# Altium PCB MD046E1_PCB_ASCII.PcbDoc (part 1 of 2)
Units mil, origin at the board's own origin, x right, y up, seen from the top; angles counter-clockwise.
Board outline 4143.7 x 2795.28 mil, 4 copper layers (Top Layer, Signal Layer 1, Signal Layer 2, Bottom Layer), stack 62.8 mil thick; 159 components, 76 nets, 432 pads, 579 vias.
Unrouted connection lines stored in the file: 13.
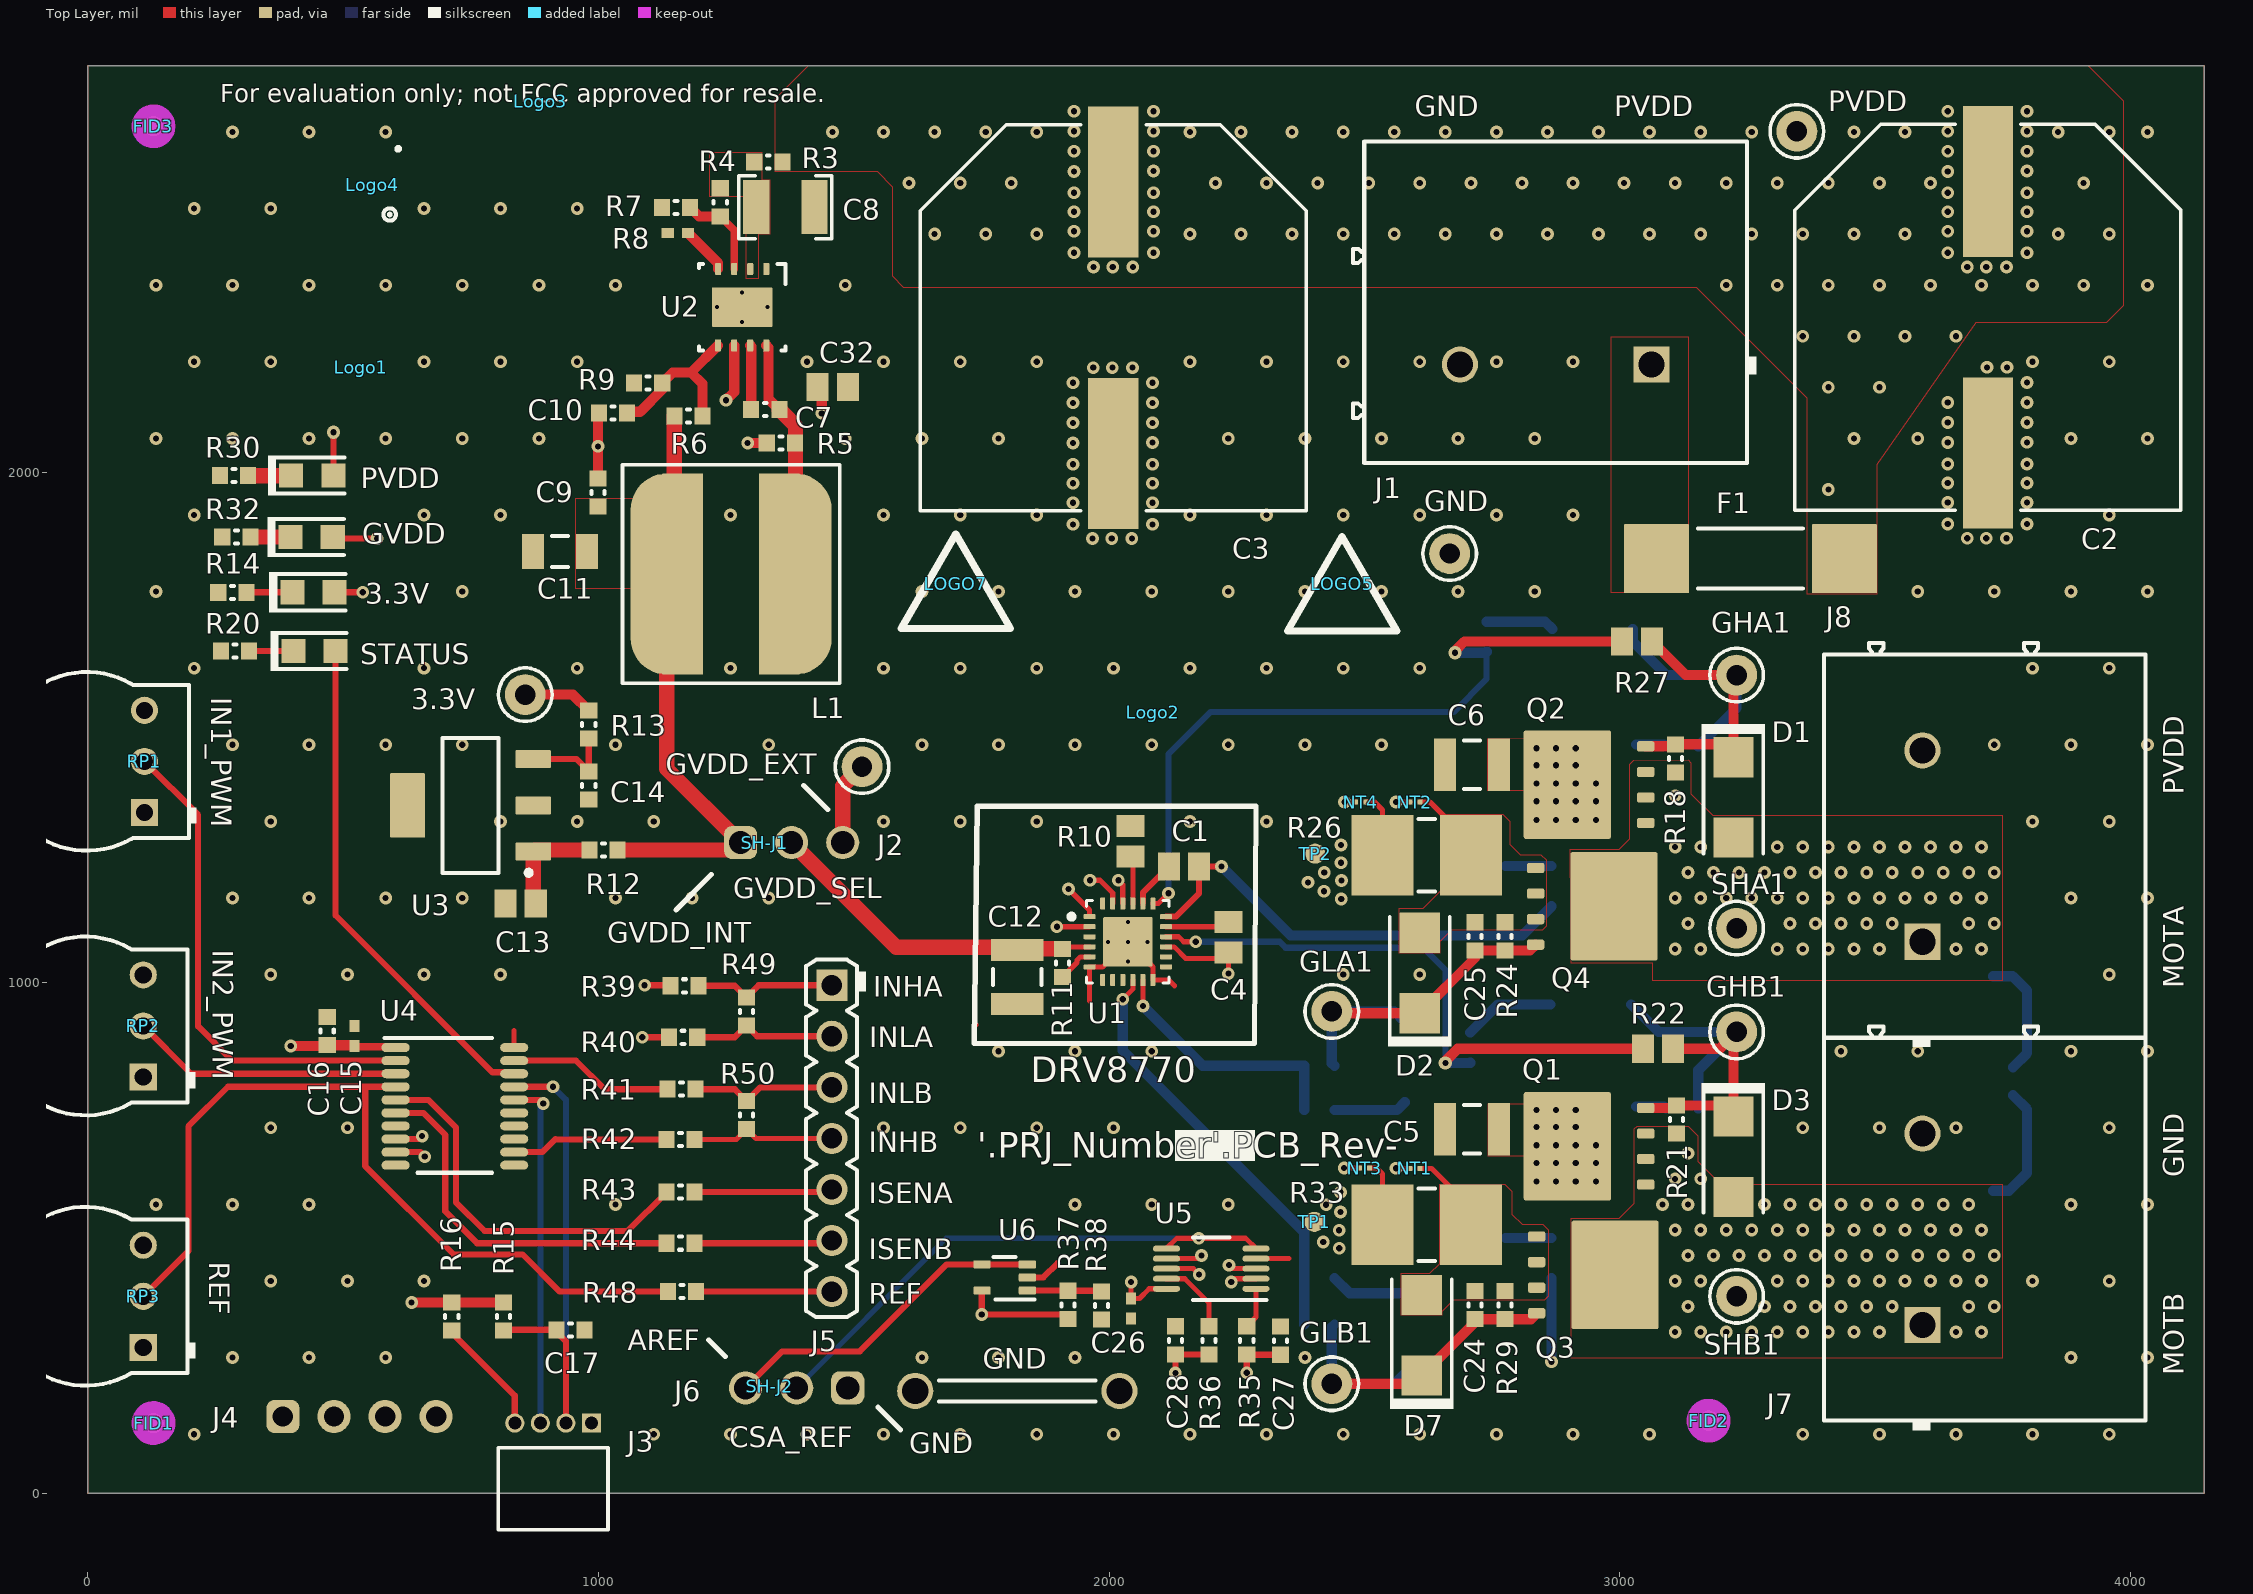
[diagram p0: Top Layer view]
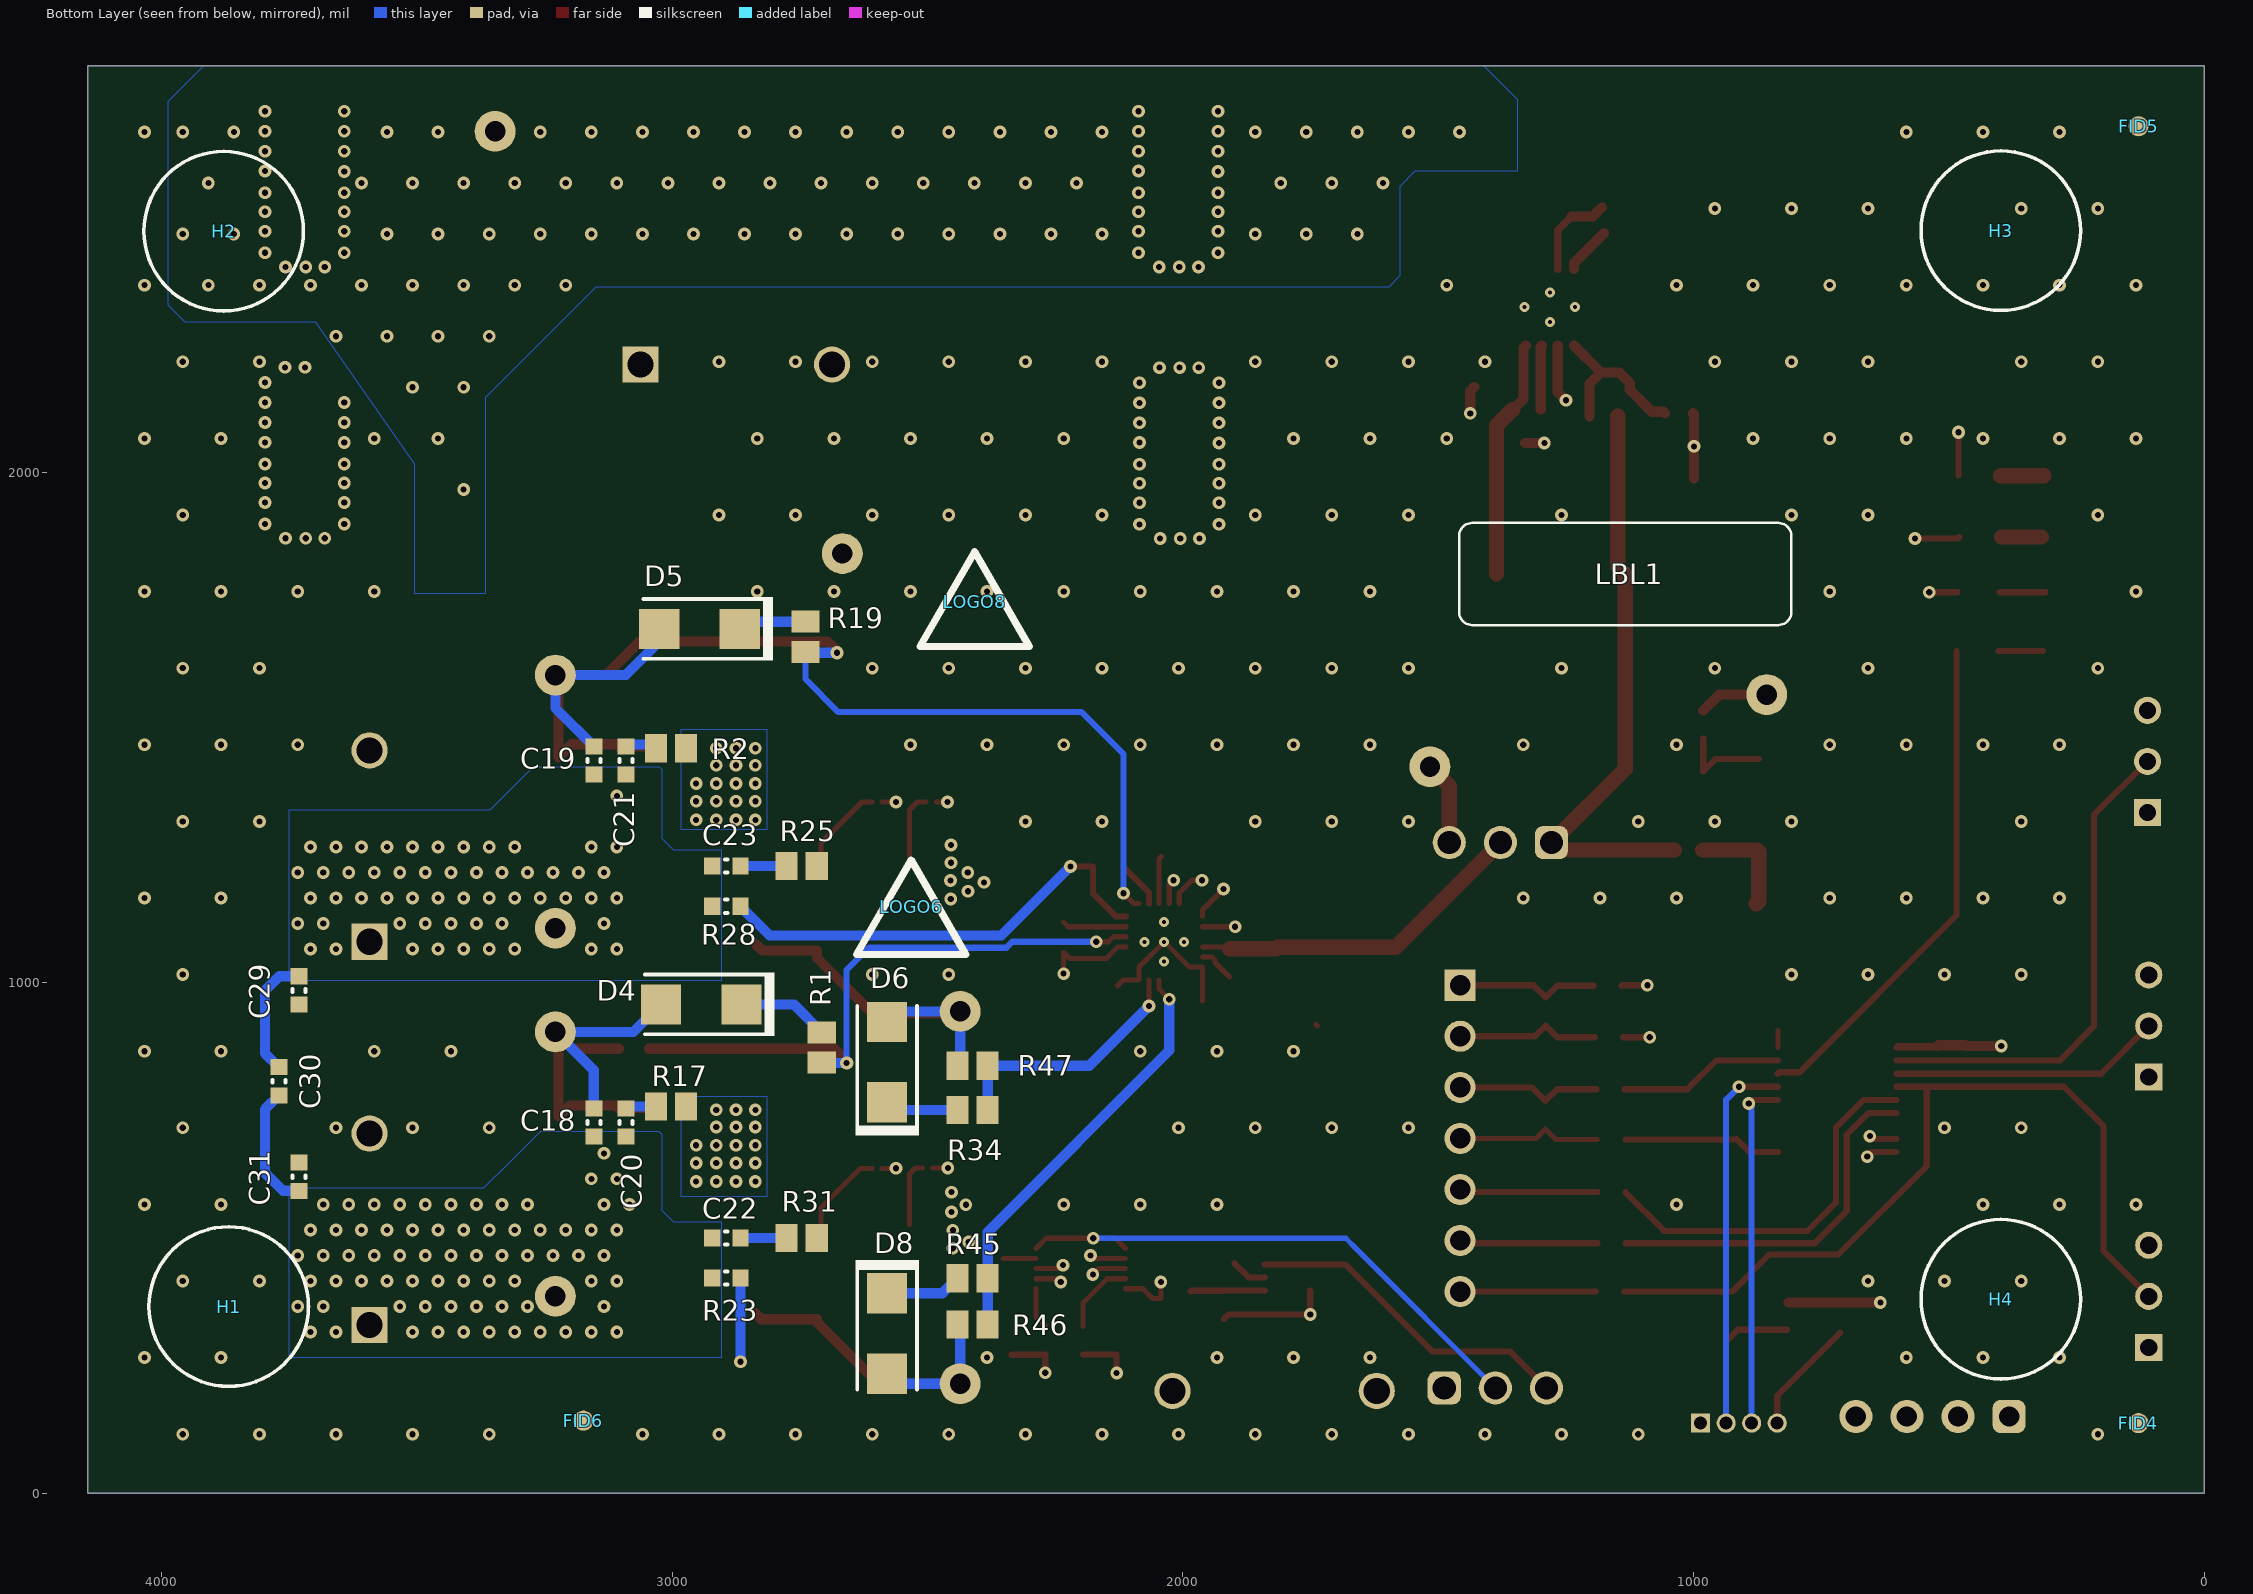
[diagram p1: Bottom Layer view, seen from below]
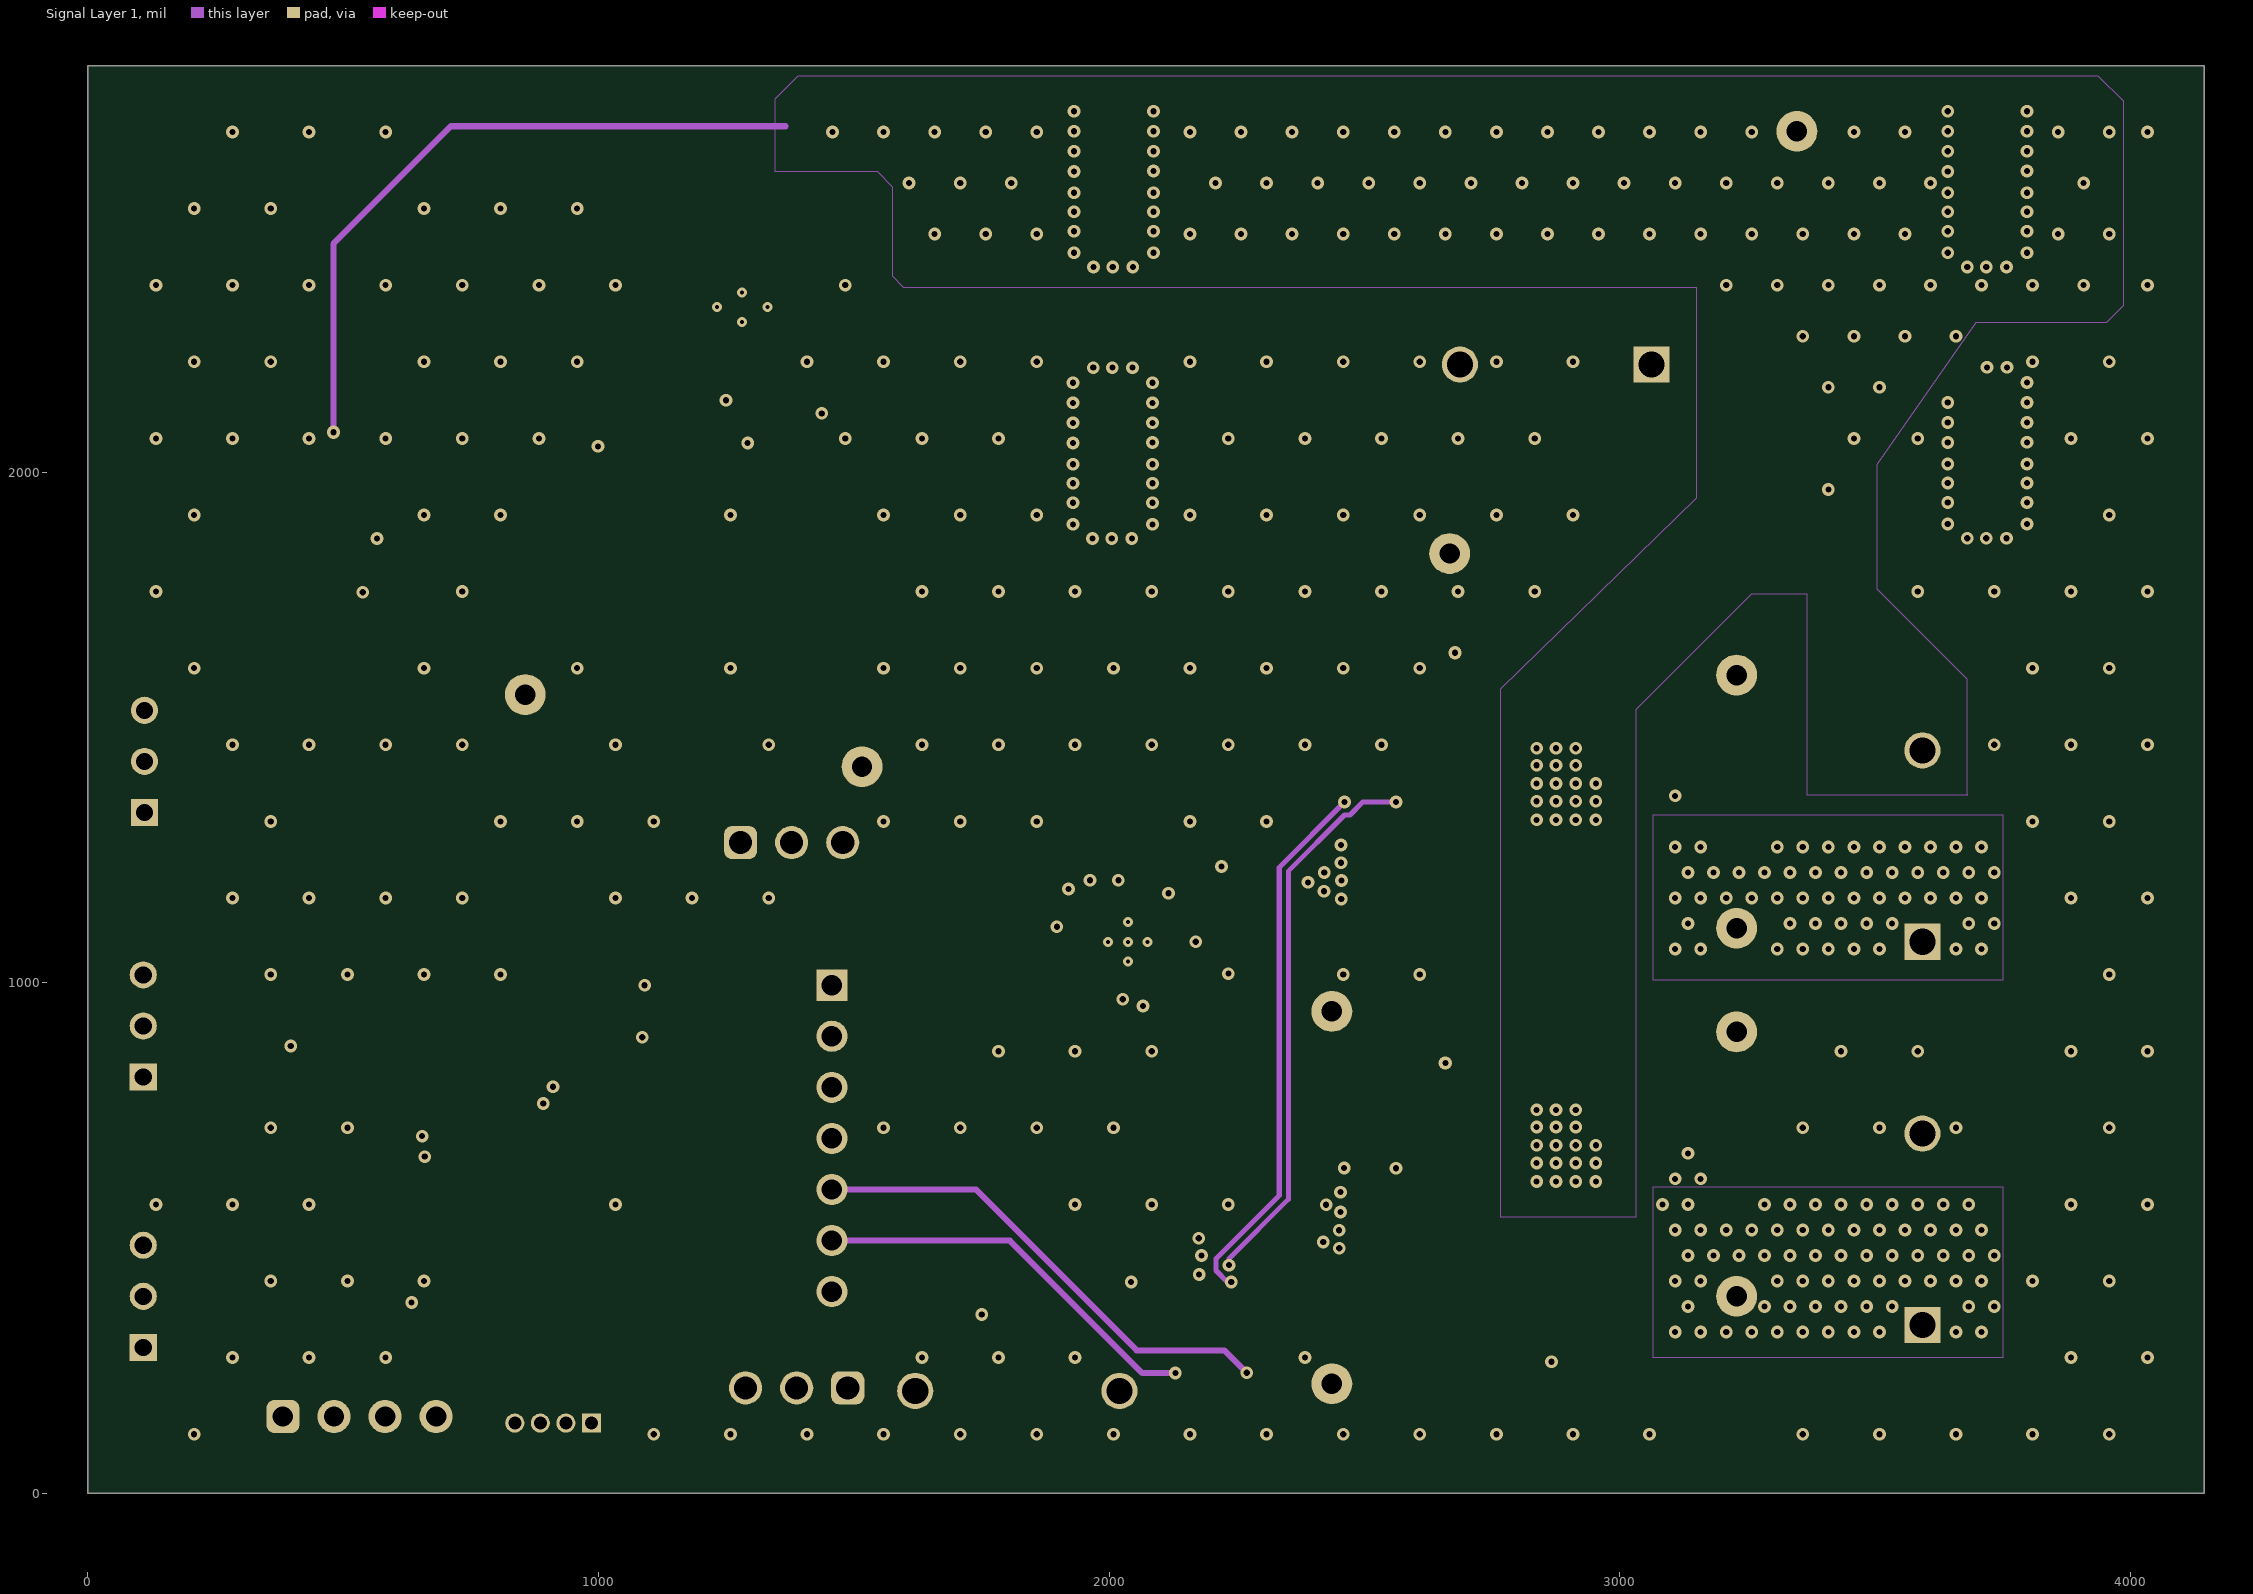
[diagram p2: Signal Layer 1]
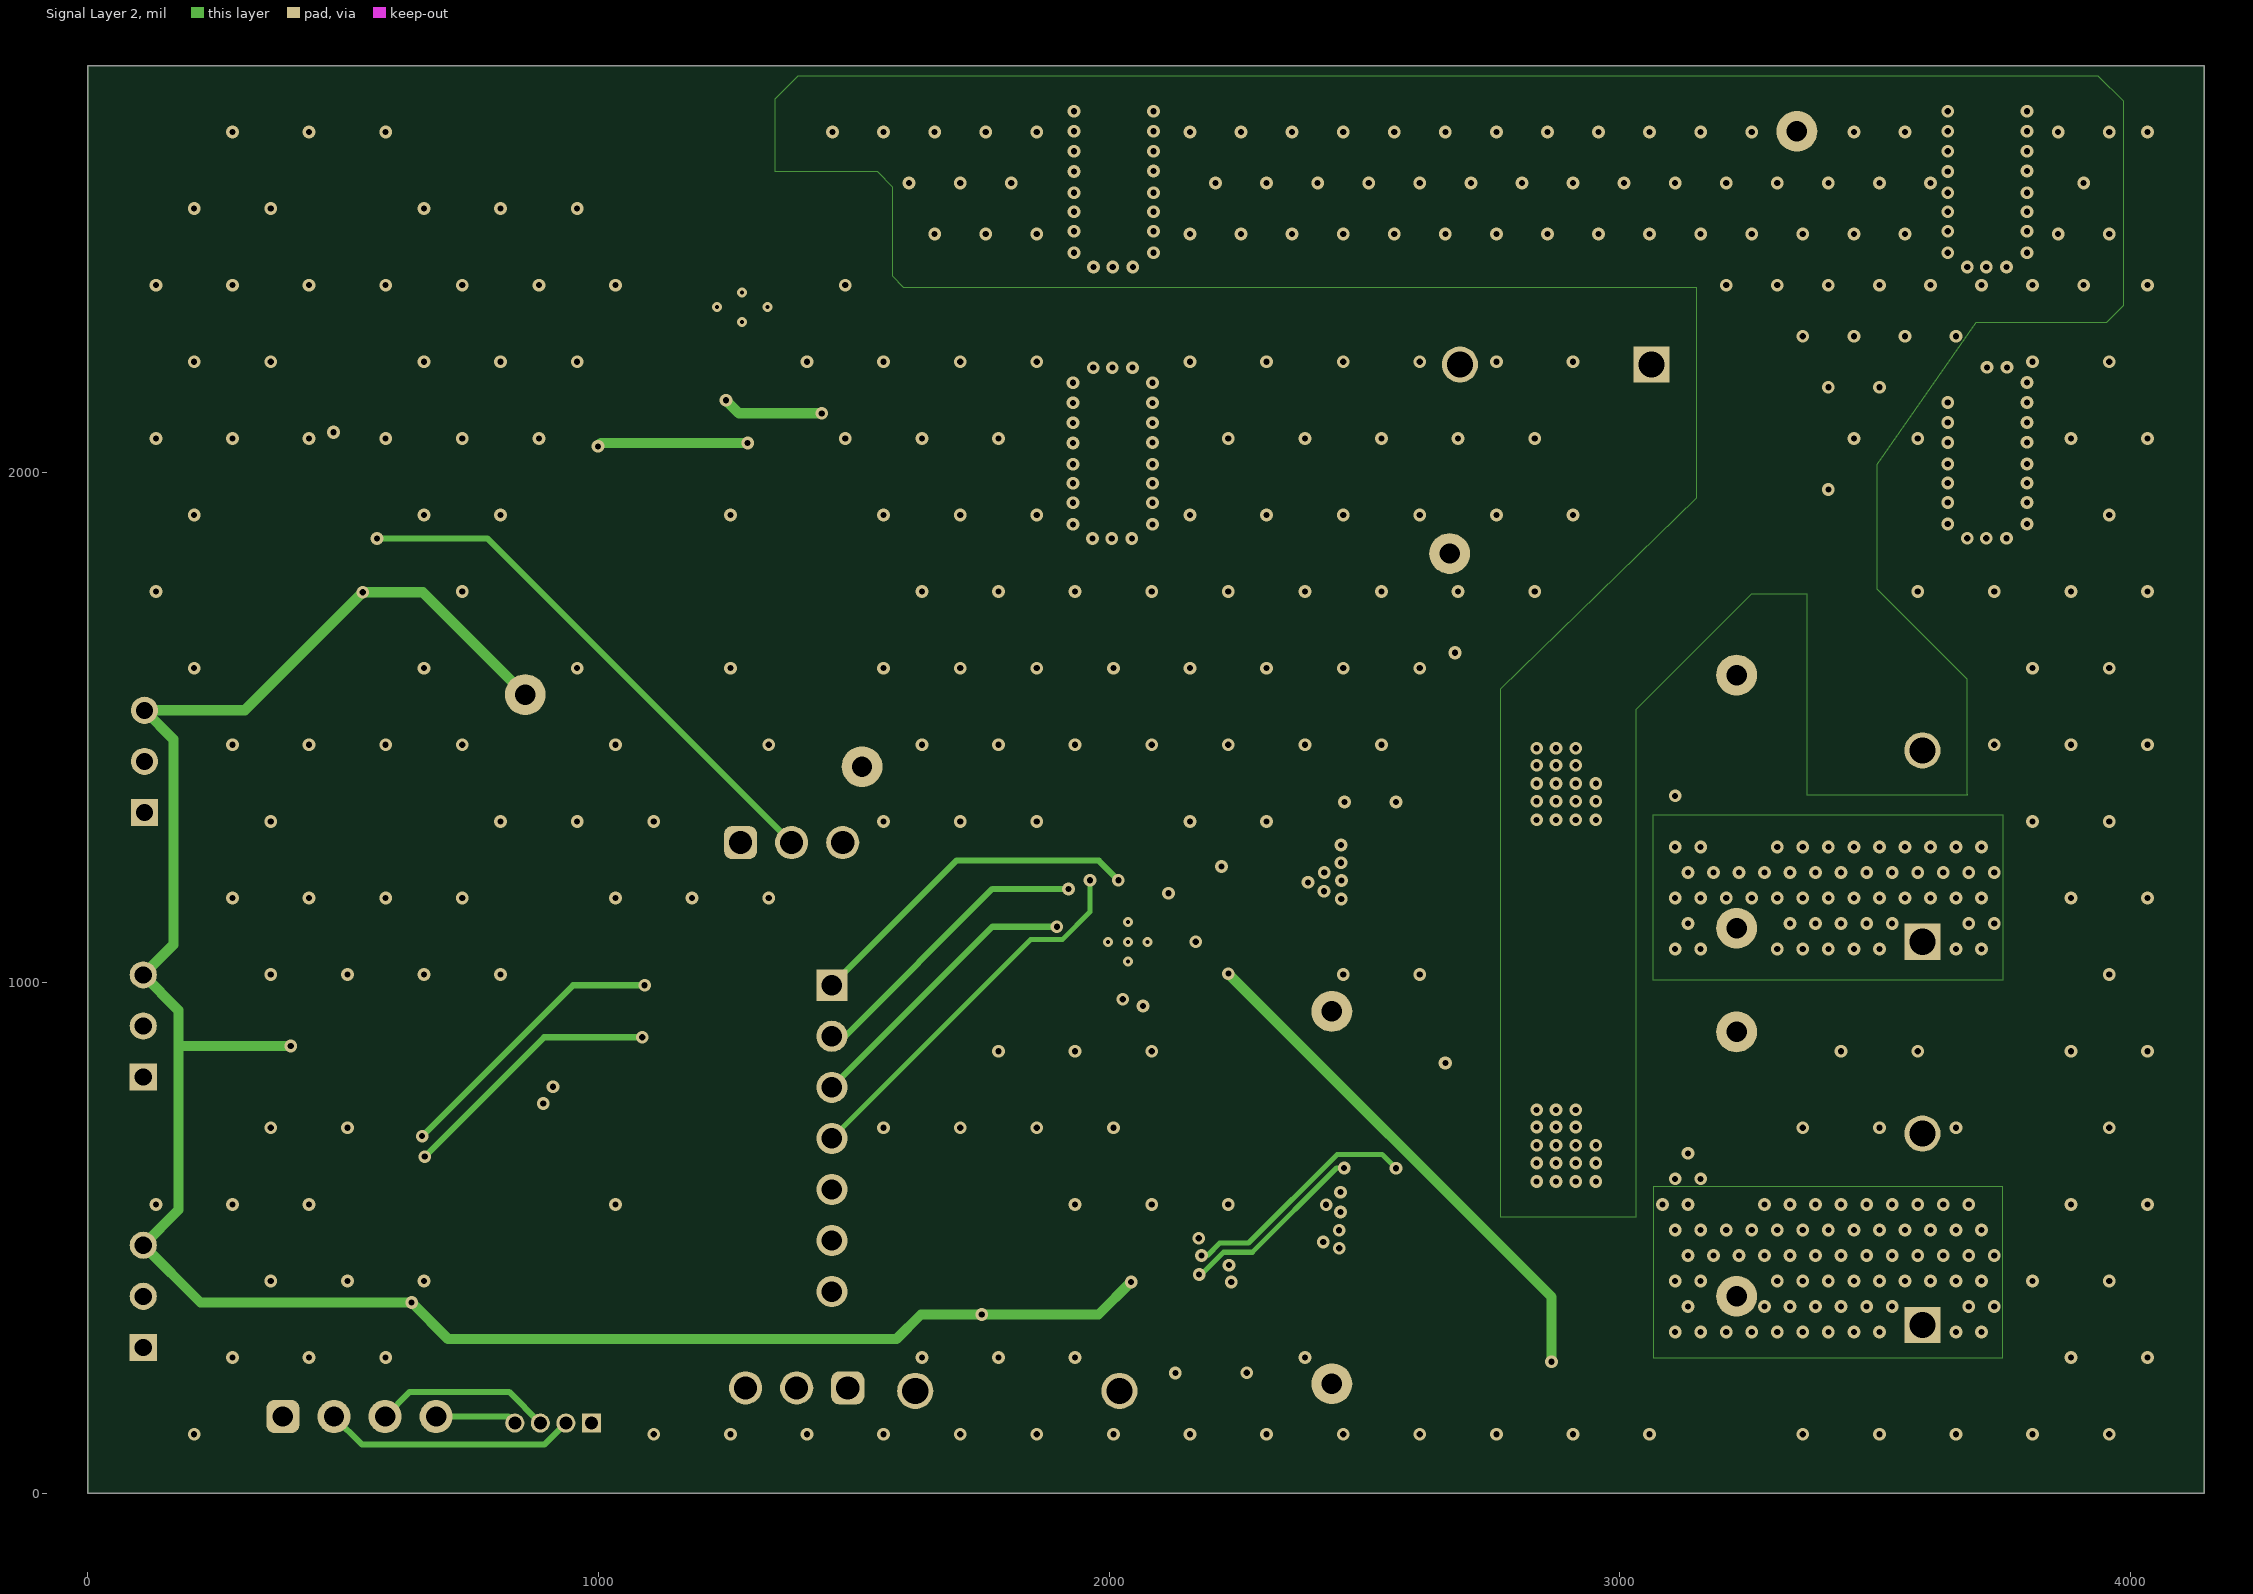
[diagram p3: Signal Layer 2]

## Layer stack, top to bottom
Top Solder: solder mask 0.4, Solder Resist, Dk 3.5
Top Layer: signal copper 2.8
Dielectric 1: prepreg 8, FR-4, Dk 4.2
Signal Layer 1: signal copper 1.4
Dielectric 2: core 38.4, FR-4, Dk 4.2
Signal Layer 2: signal copper 1.4
Dielectric 3: prepreg 8, FR-4, Dk 4.2
Bottom Layer: signal copper 2.8
Bottom Solder: solder mask 0.4, Solder Resist, Dk 3.5

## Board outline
0,0 4143.7,0 4143.7,2795.28 0,2795.28

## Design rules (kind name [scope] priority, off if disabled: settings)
AcuteAngle [All] p0: scope1count=1 scope1_0_kind=Board scope1_0_value=Board scope2count=1 scope2_0_kind=Board scope2_0_value=Board commentlength=0 minimum=4.50000000000000E+0001
AcuteAngle [All] p1: minimum=4.50000000000000E+0001 checktracksonly=FALSE
AssemblyTestPointUsage [All] p0: scope1count=1 scope1_0_kind=Board scope1_0_value=Board scope2count=1 scope2_0_kind=Board scope2_0_value=Board commentlength=0
AssemblyTestPointUsage [All] p1: valid=2
AssemblyTestpoint [All] p0: scope1count=1 scope1_0_kind=Board scope1_0_value=Board scope2count=1 scope2_0_kind=Board scope2_0_value=Board commentlength=0
BoardOutlineClearance [All] p0 off: scope1count=1 scope1_0_kind=Board scope1_0_value=Board scope2count=1 scope2_0_kind=Board scope2_0_value=Board commentlength=172 gap=75 // Protel DXP Scope 1 Expression Was: OnCopper and Not InComponentClass('Logo') and not InComponentClass('FiducialMark') and not InRegion(1000,500,4000,800) and not InPoly
BoardOutlineClearance BoardOutlineClearance_Poly [All] p0 off: scope1count=1 scope1_0_kind=Board scope1_0_value=Board scope2count=1 scope2_0_kind=Board scope2_0_value=Board commentlength=58 gap=25 // Protel DXP Scope 1 Expression Was: OnCopper and IsPoly
BoardOutlineClearance BoardOutlineClearance_MountingHoles [All] p0 off: scope1count=1 scope1_0_kind=Board scope1_0_value=Board scope2count=1 scope2_0_kind=Board scope2_0_value=Board commentlength=86 gap=39.37 // Protel DXP Scope 1 Expression Was: OnCopper and InComponentClass('Mounting Holes')
BoardOutlineClearance BoardOutlineClearance_MountingHoles [OnCopper and InComponentClass('Mounting Holes')] p1: gap=39.37 ignorepadtopadclearanceinfootprint=FALSE
BoardOutlineClearance BoardOutlineClearance_Poly [OnCopper and IsPoly] p2: gap=25 ignorepadtopadclearanceinfootprint=FALSE
BoardOutlineClearance [OnCopper and Not InComponentClass('Logo') and not InComponentClass('FiducialMark') and not InRegion(1000,500,4000,800) and not InPoly] p3: gap=75 ignorepadtopadclearanceinfootprint=FALSE
Clearance [All] p0: scope1count=1 scope1_0_kind=Board scope1_0_value=Board scope2count=1 scope2_0_kind=Board scope2_0_value=Board commentlength=0 gap=7.87
Clearance Clearance_FiducialMark [All] p0 off: scope1count=1 scope1_0_kind=Board scope1_0_value=Board scope2count=1 scope2_0_kind=Board scope2_0_value=Board commentlength=81 gap=0 // Protel DXP Scope 2 Expression Was: IsPad and InComponentClass('FiducialMark')
Clearance Clearance_Poly [All] p0 off: scope1count=1 scope1_0_kind=Board scope1_0_value=Board scope2count=1 scope2_0_kind=Board scope2_0_value=Board commentlength=48 gap=15 // Protel DXP Scope 1 Expression Was: InPolygon
Clearance Clearance_Keepouts [All] p0 off: scope1count=1 scope1_0_kind=Board scope1_0_value=Board scope2count=1 scope2_0_kind=Board scope2_0_value=Board commentlength=99 gap=0 // Protel DXP Scope 2 Expression Was: ((IsTrack Or IsArc) And Not InPoly) And IsFree and IsKeepOut
Clearance Clearance_Keepouts [((IsTrack Or IsArc) And Not InPoly) And IsFree and IsKeepOut vs ((IsTrack Or IsArc) And Not InPoly) And IsFree and IsKeepOut] p1: gap=0 ignorepadtopadclearanceinfootprint=FALSE
Clearance Clearance_Poly [InPolygon] p2: gap=15 ignorepadtopadclearanceinfootprint=TRUE
Clearance Clearance_FiducialMark [IsKeepOut and InComponentClass('FiducialMark') vs IsPad and InComponentClass('FiducialMark')] p3: gap=0 ignorepadtopadclearanceinfootprint=FALSE
Clearance [All] p4: gap=7.87 ignorepadtopadclearanceinfootprint=TRUE
ComponentClearance [All] p0: scope1count=1 scope1_0_kind=Board scope1_0_value=Board scope2count=1 scope2_0_kind=Board scope2_0_value=Board commentlength=0 gap=30 collisioncheckmode=3
ComponentClearance ComponentClearance_THtoTH [All] p0 off: scope1count=1 scope1_0_kind=Board scope1_0_value=Board scope2count=1 scope2_0_kind=Board scope2_0_value=Board commentlength=54 gap=30 collisioncheckmode=3 // Protel DXP Scope 2 Expression Was: IsThruComponent
ComponentClearance ComponentClearance_THtoSMT [All] p0 off: scope1count=1 scope1_0_kind=Board scope1_0_value=Board scope2count=1 scope2_0_kind=Board scope2_0_value=Board commentlength=53 gap=40 collisioncheckmode=3 // Protel DXP Scope 2 Expression Was: IsSMTComponent
ComponentClearance ComponentClearance_SmallPassives [All] p0 off: scope1count=1 scope1_0_kind=Board scope1_0_value=Board scope2count=1 scope2_0_kind=Board scope2_0_value=Board commentlength=508 gap=14.96 collisioncheckmode=3 // Protel DXP Scope 2 Expression Was: HasFootprint('0201*') or HasFootprint('0402*') or HasFootprint('0508') or HasFootprint('0603*') or HasFootprint('0612') or HasFootprint('0805*') or HasFootprint('0815*') or HasFootprint('0830*') or HasFootprint('1206*') or HasFootprint('1210*') or HasFootprint('1808*') or HasFootprint('1812*') or HasFootprint('1825*') or HasFootprint('2010*') or HasFootprint('2220*') or HasFootprint('2225*') or HasFootprint('2512*') or HasFootprint('2728*') or HasFootprint('3518*')
ComponentClearance ComponentClearance_MountingHoles [All] p0: scope1count=1 scope1_0_kind=ComponentClass scope1_0_value="Mounting Holes" scope2count=1 scope2_0_kind=Board scope2_0_value=Board commentlength=0 gap=250 collisioncheckmode=3
ComponentClearance ComponentClearance_ScrewToNut [All] p0 off: scope1count=1 scope1_0_kind=Board scope1_0_value=Board scope2count=1 scope2_0_kind=Board scope2_0_value=Board commentlength=71 gap=5 collisioncheckmode=3 // Protel DXP Scope 2 Expression Was: (HasFootprint('Keystone_1902C'))
ComponentClearance ComponentClearance_Logo [All] p0: scope1count=1 scope1_0_kind=ComponentClass scope1_0_value=Logo scope2count=1 scope2_0_kind=Board scope2_0_value=Board commentlength=0 gap=50 collisioncheckmode=3
ComponentClearance ComponentClearance_Shunt [All] p0: scope1count=1 scope1_0_kind=ComponentClass scope1_0_value=Header scope2count=1 scope2_0_kind=ComponentClass scope2_0_value=Shunt commentlength=0 gap=0 collisioncheckmode=3
ComponentClearance ComponentClearance_MountingHoles_FiducialMarks [All] p0: scope1count=1 scope1_0_kind=ComponentClass scope1_0_value="Mounting Holes" scope2count=1 scope2_0_kind=ComponentClass scope2_0_value=FiducialMark commentlength=0 gap=50 collisioncheckmode=3
ComponentClearance ComponentClearance_MountingHoles_FiducialMarks [InComponentClass('Mounting Holes') vs InComponentClass('FiducialMark')] p1: gap=50 collisioncheckmode=3 verticalgap=10 showdistances=FALSE
ComponentClearance ComponentClearance_Shunt [InComponentClass('Header') vs InComponentClass('Shunt')] p2: gap=0 collisioncheckmode=3 verticalgap=0 showdistances=FALSE
ComponentClearance ComponentClearance_Logo [InComponentClass('Logo')] p3: gap=50 collisioncheckmode=3 verticalgap=10 showdistances=FALSE
ComponentClearance ComponentClearance_ScrewToNut [(HasFootprint('NY PMS 440 0025 PH')) vs (HasFootprint('Keystone_1902C'))] p4: gap=5 collisioncheckmode=3 verticalgap=10 showdistances=FALSE
ComponentClearance ComponentClearance_MountingHoles [InComponentClass('Mounting Holes')] p5: gap=250 collisioncheckmode=3 verticalgap=100000 showdistances=FALSE
ComponentClearance ComponentClearance_SmallPassives [HasFootprint('0201*') or HasFootprint('0402*') or HasFootprint('0508') or HasFootprint('0603*') or HasFootprint('0612') or HasFootprint('0805*') or HasFootprint('0815*') or HasFootprint('0830*') or HasFootprint('1206*') or HasFootprint('1210*') or HasFootprint('1808*') or HasFootprint('1812*') or HasFootprint('1825*') or HasFootprint('2010*') or HasFootprint('2220*') or HasFootprint('2225*') or HasFootprint('2512*') or HasFootprint('2728*') or HasFootprint('3518*') vs HasFootprint('0201*') or HasFootprint('0402*') or HasFootprint('0508') or HasFootprint('0603*') or HasFootprint('0612') or HasFootprint('0805*') or HasFootprint('0815*') or HasFootprint('0830*') or HasFootprint('1206*') or HasFootprint('1210*') or HasFootprint('1808*') or HasFootprint('1812*') or HasFootprint('1825*') or HasFootprint('2010*') or HasFootprint('2220*') or HasFootprint('2225*') or HasFootprint('2512*') or HasFootprint('2728*') or HasFootprint('3518*')] p6: gap=14.96 collisioncheckmode=3 verticalgap=10 showdistances=FALSE
ComponentClearance ComponentClearance_THtoSMT [IsThruComponent vs IsSMTComponent] p7: gap=40 collisioncheckmode=3 verticalgap=30 showdistances=FALSE
ComponentClearance ComponentClearance_THtoTH [IsThruComponent vs IsThruComponent] p8: gap=30 collisioncheckmode=3 verticalgap=30 showdistances=FALSE
ComponentClearance [All] p9: gap=30 collisioncheckmode=3 verticalgap=10 showdistances=FALSE
DiffPairsRouting [All] p0: scope1count=1 scope1_0_kind=Board scope1_0_value=Board scope2count=1 scope2_0_kind=Board scope2_0_value=Board commentlength=0
DiffPairsRouting [All] p1: maxlimit=100 minlimit=10 mostfreqgap=10 toplayer_minwidth=15 toplayer_maxwidth=15 toplayer_prefwidth=15 midlayer1_minwidth=15 midlayer1_maxwidth=15 midlayer1_prefwidth=15 midlayer2_minwidth=15 midlayer2_maxwidth=15 midlayer2_prefwidth=15 bottomlayer_minwidth=15 bottomlayer_maxwidth=15 bottomlayer_prefwidth=15 maxuncoupledlength=1000
FabricationTestPointUsage TestPointUsage [All] p0: scope1count=1 scope1_0_kind=Board scope1_0_value=Board scope2count=1 scope2_0_kind=Board scope2_0_value=Board commentlength=0 valid=2 allowmultiple=FALSE
FabricationTestPointUsage TestPointUsage [All] p1: valid=2 allowmultiple=FALSE
FabricationTestpoint Testpoint [All] p0: scope1count=1 scope1_0_kind=Board scope1_0_value=Board scope2count=1 scope2_0_kind=Board scope2_0_value=Board commentlength=0 side=3 testpointundercomponent=TRUE minsize=40 maxsize=100 preferedsize=60 minholesize=0 maxholesize=40 preferedholesize=32 testpointgrid=1
FabricationTestpoint Testpoint [All] p1: side=3 testpointundercomponent=TRUE minsize=40 maxsize=100 preferedsize=60 minholesize=0 maxholesize=40 preferedholesize=32 testpointgrid=1 allowsidetop=TRUE allowsidebottom=TRUE usegrid=TRUE gridtolerance=0.01
FanoutControl Fanout_Small [All] p0 off: scope1count=1 scope1_0_kind=Board scope1_0_value=Board scope2count=1 scope2_0_kind=Board scope2_0_value=Board commentlength=84 // Protel DXP Scope 1 Expression Was: (CompPinCount < 5)   Fanout_Small (Default Rule)
FanoutControl Fanout_Default [All] p0: scope1count=1 scope1_0_kind=Board scope1_0_value=Board scope2count=1 scope2_0_kind=Board scope2_0_value=Board commentlength=30 // Fanout_Default (Default Rule)
FanoutControl Fanout_SOIC [All] p0 off: scope1count=1 scope1_0_kind=Board scope1_0_value=Board scope2count=1 scope2_0_kind=Board scope2_0_value=Board commentlength=71 // Protel DXP Scope 1 Expression Was: IsSOIC   Fanout_SOIC (Default Rule)
FanoutControl Fanout_BGA [All] p0 off: scope1count=1 scope1_0_kind=Board scope1_0_value=Board scope2count=1 scope2_0_kind=Board scope2_0_value=Board commentlength=69 // Protel DXP Scope 1 Expression Was: IsBGA   Fanout_BGA (Default Rule)
FanoutControl Fanout_LCC [All] p0 off: scope1count=1 scope1_0_kind=Board scope1_0_value=Board scope2count=1 scope2_0_kind=Board scope2_0_value=Board commentlength=69 // Protel DXP Scope 1 Expression Was: IsLCC   Fanout_LCC (Default Rule)
FanoutControl Fanout_LCC [IsLCC] p1: bgadir=Out bgaviamode=Centered fanoutstyle=Auto fanoutdirection=Alternating viagrid=1 // Fanout_LCC (Default Rule)
FanoutControl Fanout_BGA [IsBGA] p2: bgadir=Out bgaviamode=Centered fanoutstyle=Auto fanoutdirection=Alternating viagrid=1 // Fanout_BGA (Default Rule)
FanoutControl Fanout_Default [All] p4: bgadir=Out bgaviamode=Centered fanoutstyle=Auto fanoutdirection=Alternating viagrid=1 // Fanout_Default (Default Rule)
FanoutControl Fanout_Small [(CompPinCount < 5)] p5: bgadir=Out bgaviamode=Centered fanoutstyle=Auto fanoutdirection=OutThenIn viagrid=1 // Fanout_Small (Default Rule)
Height [All] p0: scope1count=1 scope1_0_kind=Board scope1_0_value=Board scope2count=1 scope2_0_kind=Board scope2_0_value=Board commentlength=0
HoleSize [All] p0: scope1count=1 scope1_0_kind=Board scope1_0_value=Board scope2count=1 scope2_0_kind=Board scope2_0_value=Board commentlength=0 absolutevalues=TRUE maxlimit=251 minlimit=7.87 maxpercent=80.000 minpercent=20.000
HoleSize [All] p1: absolutevalues=TRUE maxlimit=251 minlimit=7.87 maxpercent=80.000 minpercent=20.000
HoleToHoleClearance [All] p0: scope1count=1 scope1_0_kind=Board scope1_0_value=Board scope2count=1 scope2_0_kind=Board scope2_0_value=Board commentlength=0
LayerPairs [All] p0: scope1count=1 scope1_0_kind=Board scope1_0_value=Board scope2count=1 scope2_0_kind=Board scope2_0_value=Board commentlength=0 enforce=TRUE
MinimumAnnularRing [All] p0: scope1count=1 scope1_0_kind=Board scope1_0_value=Board scope2count=1 scope2_0_kind=Board scope2_0_value=Board commentlength=0 minimumring=7.87
MinimumAnnularRing MinimumAnnularRing_ThermalPadVias [All] p0 off: scope1count=1 scope1_0_kind=Board scope1_0_value=Board scope2count=1 scope2_0_kind=Board scope2_0_value=Board commentlength=63 minimumring=5.91 // Protel DXP Scope 1 Expression Was: IsVia and InAnyComponent
MinimumAnnularRing MinimumAnnularRing_ThermalPadVias [IsVia and InAnyComponent] p1: minimumring=5.91
MinimumAnnularRing [All] p2: minimumring=7.87
MinimumSolderMaskSliver [All] p0: scope1count=1 scope1_0_kind=Board scope1_0_value=Board scope2count=1 scope2_0_kind=Board scope2_0_value=Board commentlength=0
MinimumSolderMaskSliver MinimumSolderMaskSliver_Logo [All] p0: scope1count=1 scope1_0_kind=ComponentClass scope1_0_value=Logo scope2count=1 scope2_0_kind=ComponentClass scope2_0_value=Logo commentlength=0
MinimumSolderMaskSliver MinimumSolderMaskSliver_Logo [InComponentClass('Logo') vs InComponentClass('Logo')] p1: minsoldermaskwidth=0.7
MinimumSolderMaskSliver [All] p2: minsoldermaskwidth=3.94
NetAntennae [All] p0: scope1count=1 scope1_0_kind=Board scope1_0_value=Board scope2count=1 scope2_0_kind=Board scope2_0_value=Board commentlength=0
PasteMaskExpansion [All] p0: scope1count=1 scope1_0_kind=Board scope1_0_value=Board scope2count=1 scope2_0_kind=Board scope2_0_value=Board commentlength=0 expansion=0
PlaneClearance [All] p0: scope1count=1 scope1_0_kind=Board scope1_0_value=Board scope2count=1 scope2_0_kind=Board scope2_0_value=Board commentlength=0 clearance=20
PlaneConnect [All] p0: scope1count=1 scope1_0_kind=Board scope1_0_value=Board scope2count=1 scope2_0_kind=Board scope2_0_value=Board commentlength=0 planeconnectstyle=Direct reliefexpansion=10 reliefentries=4 reliefconductorwidth=10 reliefairgap=10
PlaneConnect [All] p1: planeconnectstyle=Direct reliefexpansion=10 reliefentries=4 reliefconductorwidth=10 reliefairgap=10
PolygonConnect PolygonConnect_4 [All] p0 off: scope1count=1 scope1_0_kind=Board scope1_0_value=Board scope2count=1 scope2_0_kind=Board scope2_0_value=Board commentlength=79 connectstyle=Direct reliefconductorwidth=10 reliefentries=4 polygonreliefangle="90 Angle" // Protel DXP Scope 2 Expression Was: IsNamedPolygon('TOP_LAYER_NETC8_1_P000')
PolygonConnect PolygonConnect_3 [All] p0 off: scope1count=1 scope1_0_kind=Board scope1_0_value=Board scope2count=1 scope2_0_kind=Board scope2_0_value=Board commentlength=76 connectstyle=Direct reliefconductorwidth=10 reliefentries=4 polygonreliefangle="90 Angle" // Protel DXP Scope 2 Expression Was: IsNamedPolygon('TOP_LAYER_PVDD_P008')
PolygonConnect PolygonConnect_2 [All] p0 off: scope1count=1 scope1_0_kind=Board scope1_0_value=Board scope2count=1 scope2_0_kind=Board scope2_0_value=Board commentlength=76 connectstyle=Direct reliefconductorwidth=10 reliefentries=4 polygonreliefangle="90 Angle" // Protel DXP Scope 2 Expression Was: IsNamedPolygon('TOP_LAYER_PVDD_P014')
PolygonConnect PolygonConnect_1 [All] p0 off: scope1count=1 scope1_0_kind=Board scope1_0_value=Board scope2count=1 scope2_0_kind=Board scope2_0_value=Board commentlength=79 connectstyle=Direct reliefconductorwidth=10 reliefentries=4 polygonreliefangle="90 Angle" // Protel DXP Scope 2 Expression Was: IsNamedPolygon('TOP_LAYER_NETF1_2_P010')
PolygonConnect [All] p0: scope1count=1 scope1_0_kind=Board scope1_0_value=Board scope2count=1 scope2_0_kind=Board scope2_0_value=Board commentlength=0 connectstyle=Direct reliefconductorwidth=10 reliefentries=4 polygonreliefangle="90 Angle"
PolygonConnect PolygonConnect_4 [All vs IsNamedPolygon('TOP_LAYER_NETC8_1_P000')] p1: connectstyle=Direct reliefconductorwidth=10 reliefentries=4 polygonreliefangle="90 Angle" airgapwidth=10
PolygonConnect PolygonConnect_3 [All vs IsNamedPolygon('TOP_LAYER_PVDD_P008')] p2: connectstyle=Direct reliefconductorwidth=10 reliefentries=4 polygonreliefangle="90 Angle" airgapwidth=10
PolygonConnect PolygonConnect_2 [All vs IsNamedPolygon('TOP_LAYER_PVDD_P014')] p3: connectstyle=Direct reliefconductorwidth=10 reliefentries=4 polygonreliefangle="90 Angle" airgapwidth=10
PolygonConnect PolygonConnect_1 [All vs IsNamedPolygon('TOP_LAYER_NETF1_2_P010')] p4: connectstyle=Direct reliefconductorwidth=10 reliefentries=4 polygonreliefangle="90 Angle" airgapwidth=10
PolygonConnect [All] p5: connectstyle=Direct reliefconductorwidth=10 reliefentries=4 polygonreliefangle="90 Angle" airgapwidth=10
RoutingCorners [All] p0: scope1count=1 scope1_0_kind=Board scope1_0_value=Board scope2count=1 scope2_0_kind=Board scope2_0_value=Board commentlength=0 cornerstyle=45-Degree minsetback=100 maxsetback=100
RoutingLayers [All] p0: scope1count=1 scope1_0_kind=Board scope1_0_value=Board scope2count=1 scope2_0_kind=Board scope2_0_value=Board commentlength=0 top layer=Automatic mid layer 1=Automatic mid layer 2=Automatic bottom layer=Automatic
RoutingPriority [All] p0: scope1count=1 scope1_0_kind=Board scope1_0_value=Board scope2count=1 scope2_0_kind=Board scope2_0_value=Board commentlength=0
RoutingTopology [All] p0: scope1count=1 scope1_0_kind=Board scope1_0_value=Board scope2count=1 scope2_0_kind=Board scope2_0_value=Board commentlength=0 topology=Shortest
RoutingVias [All] p0: scope1count=1 scope1_0_kind=Board scope1_0_value=Board scope2count=1 scope2_0_kind=Board scope2_0_value=Board commentlength=0 holewidth=16 width=34 viastyle="Through Hole" minholewidth=7.87 minwidth=26 maxholewidth=40 maxwidth=65
RoutingVias ThermalPadVias [All] p0 off: scope1count=1 scope1_0_kind=Board scope1_0_value=Board scope2count=1 scope2_0_kind=Board scope2_0_value=Board commentlength=63 holewidth=7.87 width=19.68 viastyle="Through Hole" minholewidth=7.87 minwidth=19.68 maxholewidth=12.99 maxwidth=23.62 // Protel DXP Scope 1 Expression Was: IsVia and InAnyComponent
RoutingVias ThermalPadVias [IsVia and InAnyComponent] p1: holewidth=7.87 width=19.68 viastyle="Through Hole" minholewidth=7.87 minwidth=19.68 maxholewidth=12.99 maxwidth=23.62
RoutingVias [All] p2: holewidth=16 width=34 viastyle="Through Hole" minholewidth=7.87 minwidth=26 maxholewidth=40 maxwidth=65
ShortCircuit [All] p0: scope1count=1 scope1_0_kind=Board scope1_0_value=Board scope2count=1 scope2_0_kind=Board scope2_0_value=Board commentlength=0 allowed=FALSE
SilkToBoardRegionClearance [All] p0 off: scope1count=1 scope1_0_kind=Board scope1_0_value=Board scope2count=1 scope2_0_kind=Board scope2_0_value=Board commentlength=130 // Protel DXP Scope 1 Expression Was: Not ((IsComment or IsDesignator) And (Hide <> 'False')) and not InRegion(1000,500,4000,800)
SilkToBoardRegionClearance [Not ((IsComment or IsDesignator) And (Hide <> 'False')) and not InRegion(1000,500,4000,800)] p1:
SilkToSilkClearance [All] p0: scope1count=1 scope1_0_kind=Board scope1_0_value=Board scope2count=1 scope2_0_kind=Board scope2_0_value=Board commentlength=0
SilkToSilkClearance SilkToSilkClearance_Pb-FreeLogo [All] p0 off: scope1count=1 scope1_0_kind=Board scope1_0_value=Board scope2count=1 scope2_0_kind=Board scope2_0_value=Board commentlength=120 // Protel DXP Scope 2 Expression Was: (HasFootprint('Pb-Free_Overlay_Medium') OR HasFootprint('Pb-Free_Overlay_Small'))
SilkToSilkClearance SilkToSilkClearance_Pb-FreeLogo [(HasFootprint('Pb-Free_Overlay_Medium') OR HasFootprint('Pb-Free_Overlay_Small')) vs (HasFootprint('Pb-Free_Overlay_Medium') OR HasFootprint('Pb-Free_Overlay_Small'))] p1: silktosilkclearance=0
SilkToSilkClearance [All] p2: silktosilkclearance=3.94
SilkToSolderMaskClearance "Silk to Solder Mask Opening" [All] p0: scope1count=1 scope1_0_kind=Board scope1_0_value=Board scope2count=1 scope2_0_kind=Board scope2_0_value=Board commentlength=0
SilkToSolderMaskClearance SilkToComponentPadClearance [All] p0 off: scope1count=1 scope1_0_kind=Board scope1_0_value=Board scope2count=1 scope2_0_kind=Board scope2_0_value=Board commentlength=87 // Protel DXP Scope 1 Expression Was: (IsPad or IsFill or IsRegion) and InAnycomponent
SilkToSolderMaskClearance SilkToComponentPadClearance [(IsPad or IsFill or IsRegion) and InAnycomponent] p1: minsilkscreentomaskgap=5 clearancetoexposedcopper=TRUE
SilkToSolderMaskClearance "Silk to Solder Mask Opening" [All] p2: minsilkscreentomaskgap=3.94 clearancetoexposedcopper=FALSE
SolderMaskExpansion [All] p0: scope1count=1 scope1_0_kind=Board scope1_0_value=Board scope2count=1 scope2_0_kind=Board scope2_0_value=Board commentlength=0 expansion=1.97
SolderMaskExpansion [All] p1: expansion=1.97
UnRoutedNet [All] p0: scope1count=1 scope1_0_kind=Board scope1_0_value=Board scope2count=1 scope2_0_kind=Board scope2_0_value=Board commentlength=0
UnRoutedNet [All] p1: checkbadconnections=TRUE
UnpouredPolygon [All] p0: scope1count=1 scope1_0_kind=Board scope1_0_value=Board scope2count=1 scope2_0_kind=Board scope2_0_value=Board commentlength=0
Width [All] p0: scope1count=1 scope1_0_kind=Board scope1_0_value=Board scope2count=1 scope2_0_kind=Board scope2_0_value=Board commentlength=0 maxlimit=100 minlimit=6 preferedwidth=10
Width [All] p1: maxlimit=100 minlimit=6 preferedwidth=10 checkconnectedcopper=TRUE
14 further rules are at their usual default settings.

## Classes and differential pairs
component class MD046E1_SCH: 3.3V C1 C2 C3 C4 C5 C6 C7 C8 C9 C10 C11 C12 C13 C14 C15 C16 C17 C18 C19 C20 C21 C22 C23 C24 C25 C26 C27 C28 C29 C30 C31 C32 D1 D2 D3 D4 D5 D6 D7 D8 F1 GHA1 GHB1 GLA1 GLB1 GND GVDD GVDD_EXT J1 J2 J3 J4 J5 J6 J7 J8 L1 NT1 NT2 NT3 NT4 PVDD Q1 Q2 Q3 Q4 R1 R2 R3 R4 R5 R6 R7 R8 R9 R10 R11 R12 R13 R14 R15 R16 R17 R18 R19 R20 R21 R22 R23 R24 R25 R26 R27 R28 R29 R30 R31 R32 R33 R34 R35 R36 R37 R38 R39 R40 R41 R42 R43 R44 R45 R46 R47 R48 R49 R50 RP1 RP2 RP3 SH-J1 SH-J2 SHA1 SHB1 STATUS TP1 TP2 U1 U2 U3 U4 U5 U6
component class MD046E1_Hardware: FID1 FID2 FID3 FID4 FID5 FID6 H1 H2 H3 H4 LBL1 Logo1 Logo2 Logo3 Logo4 LOGO5 LOGO6 LOGO7 LOGO8 ZZ1 ZZ2 ZZ3 ZZ4

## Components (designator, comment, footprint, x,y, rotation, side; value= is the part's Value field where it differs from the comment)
3.3V "" Keystone5000 856.3,1564.22 r90 top
3.3V "" LED_LTST-C171 441.55,1764.59 r180 top
C1 "CL21B105KAFNNNE" 0805L 2146.46,1227.86 r0 top
C2 "EEV-FK2A331M" SM_RADIAL_K16 3720.47,2303.15 r270 top
C3 "EEV-FK2A331M" SM_RADIAL_K16 2007.87,2302.41 r270 top
C4 "CL21B105KAFNNNE" 0805L 2233.07,1089.08 r270 top
C5 "CGA6M2X7R2A105K200AA" 1210_220L 2710.24,713.34 r180 top
C6 "CGA6M2X7R2A105K200AA" 1210_220L 2710.24,1427.07 r180 top
C7 "C0603C103J1RACTU" 0603L 1326.32,2122.29 r0 top
C8 "CGA6M2X7R2A105K200AA" 1210_220 1365.69,2518.94 r0 top
C9 "CGA3E2X7R2A222K080AA" 0603L 998.57,1959.89 r90 top
C10 "GRM1885C2A560JA01D" 0603L 1028.09,2115.4 r0 top
C11 "C3216X5R1E476M160AC" 1206_190L 924.38,1844.33 r180 top
C12 "CL32B106KBJNNWE" 1210_270L 1819.69,1011.33 r270 top
C13 "08053D334KAT2A" 0805L 847.23,1155.03 r180 top
C14 "C0603C104J4RACTU" 0603L 980.64,1386.49 r270 top
C15 "C1005X5R1A475K050BC" 0402_065L 521.65,895.67 r90 top
C16 "C0603C104K8RACTU" 0603L 468.5,905.51 r90 top
C17 "C0603C102J5RACAUTO" 0603L 944.88,320.42 r0 top
C18 "06031C222KAT2A" 0603L 3153.15,726.59 r270 bottom
C19 "06031C222KAT2A" 0603L 3153.15,1435.25 r270 bottom
C20 "GRM188R72A222KA01D" 0603L 3090.16,726.59 r270 bottom
C21 "GRM188R72A222KA01D" 0603L 3090.16,1435.25 r270 bottom
C22 "GRM188R72A222KA01D" 0603L 2893.7,500.21 r180 bottom
C23 "GRM188R72A222KA01D" 0603L 2893.7,1228.56 r180 bottom
C24 "06031C222KAT2A" 0603L 2716.14,368.85 r90 top
C25 "06031C222KAT2A" 0603L 2716.14,1090.89 r90 top
C26 "C0402C104K8RACAUTO" 0402L 2042.81,361.97 r270 top
C27 "885012206081" 0603L 2334.87,299.07 r90 top
C28 "885012206081" 0603L 2129.3,299.85 r90 top
C29 "06031C102JAT2A" 0603L 3730.31,985.16 r90 bottom
C30 "06031C102JAT2A" 0603L 3769.69,807.09 r270 bottom
C31 "06031C102JAT2A" 0603L 3730.31,620.08 r90 bottom
C32 "CL21B105KAFNNNE" 0805L 1458.48,2166.88 r0 top
D1 "SMAZ16-13-F" SMA 3222.05,1362.94 r270 top
D2 "SMAZ16-13-F" SMA 2608,1019.01 r90 top
D3 "SMAZ16-13-F" SMA 3222.05,659.45 r270 top
D4 "SSA24-E3/61T" SMA 2942.91,957.6 r0 bottom
D5 "SSA24-E3/61T" SMA 2946.13,1692.91 r0 bottom
D6 "SSA24-E3/61T" SMA 2578.74,844.7 r90 bottom
D7 "SMAZ16-13-F" SMA 2611.81,309.79 r90 top
D8 "SSA24-E3/61T" SMA 2578.74,313.2 r270 bottom
F1 "100VDC 30A" Fuse_0463 3255.51,1830.71 r180 top
FID1 "Fiducial" Fiducial10-20#1 128.36,137.81 r0 top
FID2 "Fiducial" Fiducial10-20#1 3173.51,142.51 r0 top
FID3 "Fiducial" Fiducial10-20#1 128.32,2677.17 r0 top
FID4 "Fiducial" Fiducial10-20#2 128.36,137.81 r0 top
FID5 "Fiducial" Fiducial10-20#2 128.32,2677.17 r0 top
FID6 "Fiducial" Fiducial10-20#2 3173.51,142.51 r0 top
GHA1 "5002" Keystone5002 3228.35,1602.57 r90 top
GHB1 "5002" Keystone5002 3228.35,903.75 r90 top
GLA1 "5002" Keystone5002 2435.74,943.82 r90 top
GLB1 "5002" Keystone5002 2435.74,214.78 r90 top
GND "5001" Keystone5001 2666.5,1840.55 r90 top
GND "D3082-05" Harwin_D3082-05 1819.89,200.79 r180 top
GVDD "" LED_LTST-C171 437.91,1872.86 r180 top
GVDD_EXT "" Keystone5000 1515.75,1423.09 r90 top
H1 "SJ61A1" Bumpon_SJ61A1 3868.11,366 r180 bottom
H2 "SJ61A1" Bumpon_SJ61A1 3877.95,2471.7 r180 bottom
H3 "SJ61A1" Bumpon_SJ61A1 397.94,2472.88 r180 bottom
H4 "SJ61A1" Bumpon_SJ61A1 397.94,380.32 r180 bottom
J1 "PVDD INPUT" Phoenix_1902547 2874.02,2332.68 r180 top
J2 "GVDD_PWR_SEL" WURTH_61300311121 1377.95,1274.44 r0 top
J3 "851-43-004-20-001000" CONN_851-43-004-20-001000 910.83,137.8 r0 top
J4 "TSW-104-07-G-S" TSW-104-07-G-S 531.75,150.63 r0 top
J5 "PBC07SFAN" Sullins_xxC07SFAN 1456.69,695.23 r270 top
J6 "GVDD_PWR_SEL" WURTH_61300311121 1387.8,206.69 r180 top
J7 "" Phoenix_1902547 3714.17,517.32 r90 top
J8 "" Phoenix_1902547 3714.17,1267.63 r90 top
L1 "SDR1006-680KL" SDR1006 1259.39,1800.44 r180 top
LBL1 "THT-14-423-10" Label_650x200 1133.41,1800.44 r180 bottom
Logo1 "CE Mark" CE_Mark_5mm 533.79,2205.07 r0 top
Logo2 "Texas Instruments" TI_Stacked_Overlay_Small 2084.64,1529.97 r0 top
Logo3 "FCC disclaimer" FCC_disclaimer 885.83,2726.38 r0 top
Logo4 "WEEE logo" WEEE_Minimum 556.89,2562.77 r0 top
LOGO5 "CAUTION HOT SURFACE" IEC_HotSurface_Small 2455.77,1781.5 r0 top
LOGO6 "CAUTION HOT SURFACE" IEC_HotSurface_Small 2531.69,1148.38 r180 bottom
LOGO7 "DANGER HIGH VOLTAGE" IEC_HighVoltage_Small 1699.34,1781.5 r0 top
LOGO8 "DANGER HIGH VOLTAGE" IEC_HighVoltage_Small 2407.44,1746.57 r180 bottom
NT1 "Net-Tie" Net-Tie_10mil 2598.43,636.66 r0 top net-tie
NT2 "Net-Tie" Net-Tie_10mil 2598.43,1353.74 r0 top net-tie
NT3 "Net-Tie" Net-Tie_10mil 2499.84,637.15 r0 top net-tie
NT4 "Net-Tie" Net-Tie_10mil 2492.48,1353.74 r0 top net-tie
PVDD "5000" Keystone5000 3346.46,2667.32 r90 top
PVDD "" LED_LTST-C171 439.28,1993.09 r180 top
Q1 "CSD19532Q5B" DNK0008A 2939.37,679.72 r180 top
Q2 "CSD19532Q5B" DNK0008A 2939.37,1387.94 r180 top
Q3 "CSD19532Q5B" DNK0008A 2947.83,427.9 r0 top
Q4 "CSD19532Q5B" DNK0008A 2945.87,1149.56 r0 top
R1 "ERJ-6GEYJ100V" 0805L 2706.69,873.03 r90 bottom
R2 "CRCW08052R70JNEA" 0805L 3001.97,1459.33 r180 bottom
R3 "CRCW06030000Z0EA" 0603L 1332.23,2607.53 r180 top
R4 "CRCW06031M00JNEA" 0603L 1238.13,2528.32 r90 top
R5 "RC0603FR-07681KL" 0603L 1356.83,2057.09 r180 top
R6 "RC0603FR-07453KL" 0603L 1175.73,2109.49 r180 top
R7 "CRCW0603330KJNEA" 0603L 1151.57,2518.14 r0 top
R8 "CRCW0402100KFKED" 0402L 1155.06,2468.34 r0 top
R9 "RC0603FR-0749K9L" 0603L 1096.99,2174.46 r0 top
R10 "CRCW08050000Z0EAHP" 0805L 2041.74,1277.08 r270 top
R11 "CRCW06030000Z0EA" 0603L 1908.27,1038.89 r90 top
R12 "CRCW06030000Z0EA" 0603L 1009.39,1259.84 r180 top
R13 "CRCW06030000Z0EA" 0603L 980.64,1505.58 r90 top
R14 "CRCW0603330RJNEA" 0603L 282.77,1764.59 r0 top
R15 "CRCW060347K0JNEA" 0603L 813.88,346.46 r90 top
R16 "CRCW06030000Z0EA" 0603L 712.4,346.46 r90 top
R17 "CRCW08052R70JNEA" 0805L 3001.97,757.87 r180 bottom
R18 "CRCW0603100KFKEA" 0603L 3108.86,1439.32 r270 top
R19 "ERJ-6GEYJ100V" 0805L 2738.94,1677.57 r90 bottom
R20 "CRCW0603330RJNEA" 0603L 287.76,1649.68 r0 top
R21 "CRCW0603100KFKEA" 0603L 3110.83,732.08 r270 top
R22 "ERJ-6GEYJ150V" 0805L 3074.41,870.82 r0 top
R23 "RCS06030000Z0EA" 0603L 2893.7,421.47 r0 bottom
R24 "CRCW0603100KFKEA" 0603L 2775.2,1090.89 r90 top
R25 "CRCW08052R70JNEA" 0805L 2746.06,1228.56 r0 bottom
R26 "LRMAP2512-R002FT4" LRMA2512_under3 2621.65,1249.36 r0 top
R27 "ERJ-6GEYJ150V" 0805L 3033.49,1668.26 r0 top
R28 "RCS06030000Z0EA" 0603L 2893.7,1149.82 r0 bottom
R29 "CRCW0603100KFKEA" 0603L 2775.2,368.85 r90 top
R30 "CRCW06034K99FKEA" 0603L 286.1,1993.09 r0 top
R31 "CRCW08052R70JNEA" 0805L 2746.06,500.21 r0 bottom
R32 "CRCW06034K99FKEA" 0603L 290.56,1872.86 r0 top
R33 "LRMAP2512-R002FT4" LRMA2512_under3 2621.65,526.33 r0 top
R34 "ERJ-6GEYJ100V" 0805L 2411.42,750.78 r0 bottom
R35 "RCS06030000Z0EA" 0603L 2269.1,299.85 r270 top
R36 "RCS06030000Z0EA" 0603L 2194.88,299.85 r270 top
R37 "CRCW0603100KFKEA" 0603L 1919.29,369.27 r270 top
R38 "CRCW0603100KFKEA" 0603L 1984.45,368.13 r90 top
R39 "RCS06030000Z0EA" 0603L 1167.89,994.09 r0 top
R40 "RCS06030000Z0EA" 0603L 1165.57,893.23 r0 top
R41 "RCS06030000Z0EA" 0603L 1162.49,791.57 r0 top
R42 "RCS06030000Z0EA" 0603L 1160.52,693.14 r0 top
R43 "RCS06030000Z0EA" 0603L 1160.52,589.99 r0 top
R44 "RCS06030000Z0EA" 0603L 1160.52,489.99 r0 top
R45 "ERJ-6GEYJ100V" 0805L 2411.42,421.47 r0 bottom
R46 "ERJ-6GEYJ150V" 0805L 2411.42,330.82 r0 bottom
R47 "ERJ-6GEYJ150V" 0805L 2411.42,837.35 r0 bottom
R48 "RCS06030000Z0EA" 0603L 1163.32,395.71 r0 top
R49 "RCS06030000Z0EA" 0603L 1289.37,943.65 r90 top
R50 "RCS06030000Z0EA" 0603L 1289.84,741.03 r270 top
RP1 "3352T-1-503LF" Bourns_3352T 110.65,1433.49 r90 top
RP2 "3352T-1-503LF" Bourns_3352T 108.27,915.35 r90 top
RP3 "3352T-1-503LF" Bourns_3352T 108.3,386.04 r90 top
SH-J1 "SNT-100-BK-G" SNT-100-BK-G 1325.7,1274.44 r0 top
SH-J2 "SNT-100-BK-G" SNT-100-BK-G 1335.27,209.82 r0 top
SHA1 "5002" Keystone5002 3228.35,1106.88 r90 top
SHB1 "5002" Keystone5002 3228.35,386.04 r90 top
STATUS "" LED_LTST-C171 443.75,1649.68 r180 top
TP1 "TP_SM_1MM" TP_SM_1MM 2401.57,531.71 r0 top
TP2 "TP_SM_1MM" TP_SM_1MM 2403.18,1252.94 r90 top
U1 "DRV8770RGE" RGE0024B-MFG 2036.22,1080.23 r0 top
U2 "LM5017SDX/NOPB" NGU0008B 1281.13,2322.83 r270 top
U3 "UA78M33CDCYR" DCY0004A_N 748.92,1347.27 r180 top
U4 "MSP430G2553IPW20" PW0020A_N 718.5,757.87 r0 top
U5 "INA2181A1DGS" DGS0010A_N 2199.61,440.12 r180 top
U6 "TLV9001IDCKR" DCK0005A_N 1795.08,422.94 r180 top
ZZ1 "This Assembly Note is for PCB labels only" AssemblyNoteLabel 185,3938 r0 top
ZZ2 "These assemblies are ESD sensitive, ESD precautions shall be observed." AssemblyNote 185,3829.11 r0 top
ZZ3 "These assemblies must be clean and free from flux and all contaminants. Use of no clean flux is not acceptable." AssemblyNote 185,3740.56 r0 top
ZZ4 "These assemblies must comply with workmanship standards IPC-A-610 Class 2, unless otherwise specified." AssemblyNote 185,3652 r0 top

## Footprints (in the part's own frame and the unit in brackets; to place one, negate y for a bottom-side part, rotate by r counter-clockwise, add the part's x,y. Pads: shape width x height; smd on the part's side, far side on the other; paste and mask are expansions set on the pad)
0402_065L [mm] "0402"
  rect 0.6x0.5 smd: 1(-0.5,0) 2(0.5,0)
0402L [mm] "0402 from SM-752 data"
  rect 0.6x0.5 smd: 1(-0.5,0) 2(0.5,0)
0603L [mm] "0603 from SM-752 data"
  rect 0.8x0.85 smd: 1(-0.7,0) 2(0.7,0)
  silkscreen extent -0.07,-0.33 0.07,0.33
0805L [mm] "0805 from SM-752 data"
  rect 1.1x1.4 smd: 1(-0.75,0) 2(0.75,0)
1206_190L [mm] "1206_190"
  rect 1.1x1.75 smd: 1(-1.35,0) 2(1.35,0)
  silkscreen extent -0.4,-0.77 0.4,0.77
1210_220 [mm] "1210"
  rect 1.3x2.7 smd: 1(-1.45,0) 2(1.45,0)
  silkscreen extent -2.32,-1.57 2.32,1.57
1210_220L [mm] "1210"
  rect 1.1x2.6 smd: 1(-1.35,0) 2(1.35,0)
  silkscreen extent -0.4,-1.2 0.4,1.2
1210_270L [mm] "1210"
  rect 1.1x2.6 smd: 1(-1.35,0) 2(1.35,0)
  silkscreen extent -0.4,-1.2 0.4,1.2
AssemblyNote [mil] "Assembly Note"
AssemblyNoteLabel [mil] "Assembly Note for PCB Labels"
Bourns_3352T [mm] "TH, 3-Leads, Body 9.53x8.89mm, Pitch 2.54mm"
  rect 1.35x1.35 hole 0.85: 1(-2.54,0)
  round 1.35 hole 0.85: 2(0,0) 3(2.54,0)
  silkscreen extent -4.44,-2.6 4.44,7.31
Bumpon_SJ61A1 [mil] "3M Cylindrical Bumpon black"
  round 1 on Mech4: 0(0,0)
  silkscreen extent -156,-156 156,156
CE_Mark_5mm [mil] "Minimum text height for CE Mark"
CONN_851-43-004-20-001000 [mm] "MILL-MAX"
  rect 0.95x0.95 hole 0.65: 1(1.905,0)
  round 0.95 hole 0.65: 2(0.635,0) 3(-0.635,0) 4(-1.905,0)
  silkscreen extent -2.73,-5.31 2.73,-1.22
DCK0005A_N [mm] "SOT353, 5-Leads, Body 2x1.3mm, Pitch 0.65mm, Lead Span 2.1mm, IPC Medium Density"
  rrect25% 0.85x0.4 smd: 1(-1.125,0.65) 2(-1.125,0) 3(-1.125,-0.65) 4(1.125,-0.65) 5(1.125,0.65)
  silkscreen extent -1.48,-1.02 0.55,1.1
DCY0004A_N [mm] "SOT223/SC73, 4-Leads, Body 6.5x3.5mm, Pitch 2.3mm, Lead Span 7mm, IPC Medium Density"
  rrect11% 1.75x0.9 smd: 1(-3.125,2.3) 2(-3.125,0) 3(-3.125,-2.3)
  rrect6% 1.75x3.2 smd: 4(3.125,0)
  silkscreen extent -3.03,-3.35 1.4,3.47
DGS0010A_N [mm] "TSSOP, 10-Leads, Body 3x3mm, Pitch 0.5mm, IPC Medium Density"
  oval 1.35x0.3 smd: 1(-2.225,1) 2(-2.225,0.5) 3(-2.225,0) 4(-2.225,-0.5) 5(-2.225,-1) 6(2.225,-1) 7(2.225,-0.5) 8(2.225,0) 9(2.225,0.5) 10(2.225,1)
  silkscreen extent -2.75,-1.55 0.9,1.55
DNK0008A [mm] "SON, 8-Leads, Body 5x6mm"
  rrect39% 0.86x0.51 smd paste-0.05 mask+0: 1(-2.82,1.905) 2(-2.82,0.635) 3(-2.82,-0.635) 4(-2.82,-1.905) 5(2.82,-1.905) 6(2.82,-0.635) 7(2.82,0.635) 8(2.82,1.905)
  rrect40% 0.25x0.555 on Top Solder: 9(-0.83,2.372) 9(-0.83,-2.372)
  rrect40% 0.25x0.555 on Top Paste: 9(-0.83,2.372) 9(-0.83,-2.372)
  rrect11% 0.95x1.13 on Top Paste: 9(-0.535,1.33) 9(-0.535,0) 9(-0.535,-1.33) 9(0.615,1.33) 9(0.615,0) 9(0.615,-1.33) 9(1.765,-1.33) 9(1.765,0) 9(1.765,1.33)
  rrect3% 3.58x4 on Top Solder: 9(0.75,0)
  rrect5% 4.34x5.4 smd paste-3 mask+0: 9(1.08,0)
FCC_disclaimer [mil]
Fiducial10-20#1 [mm]
  round 1 smd mask+0: 1(0,0)
  Top Layer keep-out circle w1.178: c0,0 r0.5
Fiducial10-20#2 [mm]
  round 1 smd far side mask+0: 1(0,0)
  Top Layer keep-out circle w1.178: c0,0 r0.5
Fuse_0463 [mm] "SMD, 2-Leads, Body 10.1x3.12mm"
  rrect3% 3.25x3.43 smd: 1(-4.675,0) 2(4.675,0)
  silkscreen extent -2.6,-1.5 2.6,1.5
Harwin_D3082-05 [mm] "Shorting Plug, 10.16mm spacing, TH"
  round 1.8 hole 1.3: 1(-5.08,0) 2(5.08,0)
  silkscreen extent -3.9,-0.53 3.9,0.53
IEC_HighVoltage_Small [mil]
  silkscreen extent -107,-88 107,97
IEC_HotSurface_Small [mil]
  silkscreen extent -107,-93 107,92
Keystone5000 [mil] "For Keystone 500x miniature loop terminals"
  round 80 hole 40: 1(0,0)
  silkscreen extent -52,-52 52,52
Keystone5001 [mil] "For Keystone 500x miniature loop terminals"
  round 80 hole 40: 1(0,0)
  silkscreen extent -52,-52 52,52
Keystone5002 [mil] "For Keystone 500x miniature loop terminals"
  round 80 hole 40: 1(0,0)
  silkscreen extent -52,-52 52,52
Label_650x200 [mil] "Thermal Transfer Label"
  round 1 on Mech14: 0(0,0)
  silkscreen extent -325,-100 325,100
LED_LTST-C171 [mm] "LITE-ON"
  rect 1.2x1.2 smd: 1(-1.05,0) 2(1.05,0)
  silkscreen extent -1.6,-1 2.2,1
LRMA2512_under3 [mm] "Chip Resistor, Body 6.3x3.2mm"
  rect 3.1x4 smd: 1(-2.2,0) 2(2.2,0)
  silkscreen extent -0.4,-1.8 0.4,1.8
Net-Tie_10mil [mil] "10mil net tie, no solder mask opening, no solder paste"
  rect 10x10 smd paste-5 mask+0: 1(-10,0) 2(10,0)
NGU0008B [mm] "SON, 8-Leads, Body 4x4mm, Pitch 0.8mm"
  rrect33% 0.6x0.3 smd: 1(-1.9,1.2) 2(-1.9,0.4) 3(-1.9,-0.4) 4(-1.9,-1.2) 5(1.9,-1.2) 6(1.9,-0.4) 7(1.9,0.4) 8(1.9,1.2)
  rrect5% 1.98x3 smd paste-1.5: 9(0,0)
  silkscreen extent -2.15,-2.15 2.15,2.15
Phoenix_1902547 [mm] "TH, 2-Leads, Body 19.04x16mm, Pitch 9.52mm"
  rect 1.8x1.8 hole 1.3: 1(-4.76,3.1)
  round 1.8 hole 1.3: 2(4.76,3.1)
  silkscreen extent -10,-8 10.09,8
PW0020A_N [mm] "TSOP, 20-Leads, Body 6.5x4.4mm, Pitch 0.65mm, IPC Medium Density"
  oval 1.4x0.45 smd: 1(-2.95,2.925) 2(-2.95,2.275) 3(-2.95,1.625) 4(-2.95,0.975) 5(-2.95,0.325) 6(-2.95,-0.325) 7(-2.95,-0.975) 8(-2.95,-1.625) 9(-2.95,-2.275) 10(-2.95,-2.925) 11(2.95,-2.925) 12(2.95,-2.275) 13(2.95,-1.625) 14(2.95,-0.975) 15(2.95,-0.325) 16(2.95,0.325) 17(2.95,0.975) 18(2.95,1.625) 19(2.95,2.275) 20(2.95,2.925)
  Top Overlay keep-out lines w0.2: -1.85,-3.3 1.85,-3.3
  silkscreen extent -3.5,-3.3 1.85,3.4
RGE0024B-MFG [mm]
  rrect40% 0.6x0.25 smd paste+0 mask+0: 1(-1.9,1.25) 2(-1.9,0.75) 3(-1.9,0.25) 4(-1.9,-0.25) 5(-1.9,-0.75) 6(-1.9,-1.25) 13(1.9,-1.25) 14(1.9,-0.75) 15(1.9,-0.25) 16(1.9,0.25) 17(1.9,0.75) 18(1.9,1.25)
  rrect40% 0.25x0.6 smd paste+0 mask+0: 7(-1.25,-1.9) 8(-0.75,-1.9) 9(-0.25,-1.9) 10(0.25,-1.9) 11(0.75,-1.9) 12(1.25,-1.9) 19(1.25,1.9) 20(0.75,1.9) 21(0.25,1.9) 22(-0.25,1.9) 23(-0.75,1.9) 24(-1.25,1.9)
  rrect4% 2.45x2.45 smd paste-1000 mask+0: 25(0,0)
  silkscreen extent -2.92,-2.05 2.05,2.05
SDR1006 [mm] "Bourns recommended land pattern"
  oval 3.6x10 smd: 1(-3.2,0) 2(3.2,0)
  rect 2x2 smd: 1(-2.4,4) 1(-2.4,-4) 2(2.4,4) 2(2.4,-4)
  silkscreen extent -5.4,-5.43 5.4,5.43
SM_RADIAL_K16 [mm] "18 x 16.5mm:  Panasonic K16 (K18 from land pattern recommendation)"
  rect 7.5x2.5 smd: 1(-6.75,0) 2(6.75,0)
  silkscreen extent -9.6,-9.6 9.6,9.6
SMA [mm] "Molded Diode, 2-Leads, Body 4.3x2.6mm, IPC Medium Density, based on OnSemi component dimensions and land pattern"
  rect 2x2 smd: 1(-2,0) 2(2,0)
  silkscreen extent -3.66,-1.57 2.79,1.57
SNT-100-BK-G [mil] "Samtec STEP model"
  round 1 on Mech3: 0(0,0)
Sullins_xxC07SFAN [mm] "Header, 2.54 mm, 7x1, TH"
  rect 1.55x1.55 hole 1.016: 1(-7.62,0)
  round 1.55 hole 1.016: 2(-5.08,0) 3(-2.54,0) 4(0,0) 5(2.54,0) 6(5.08,0) 7(7.62,0)
  silkscreen extent -8.89,-1.28 8.89,1.7
TI_Stacked_Overlay_Small [mil]
TP_SM_1MM [mm] "1mm Test Point, SMT"
  round 1 smd paste-0.5: 1(0,0)
TSW-104-07-G-S [mm] "Samtec 100mil, 1x4, 230 mil above insulator"
  rrect50% 1.65x1.65 hole 1.016: 1(-3.81,0)
  round 1.65 hole 1.016: 2(-1.27,0) 3(1.27,0) 4(3.81,0)
WEEE_Minimum [mil] "WEEElie bin"
  silkscreen extent 22,-71 54,74
WURTH_61300311121 [mm] "Header, 2.54mm, 3x1, TH"
  rrect50% 1.65x1.65 hole 1.15: 1(-2.54,0)
  round 1.65 hole 1.15: 2(0,0) 3(2.54,0)

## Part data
3.3V GVDD_EXT PVDD: library part CMP-0055137-1, "Test Point, Miniature, Red, TH"
3.3V GVDD PVDD STATUS: library part CMP-0002830-3, "LED, Green, SMD"
C1 C4 C32: library part CMP-0083859-1, "CAP, CERM, 1 µF, 25 V,+/- 10%, X7R, 0805"
C2 C3: library part CMP-0011224-2, "CAP, AL, 330 uF, 100 V, +/- 20%, 0.153 ohm, AEC-Q200 Grade 2, SMD"
C5 C6 C8: library part CMP-0009145-2, "CAP, CERM, 1 uF, 100 V, +/- 10%, X7R, AEC-Q200 Grade 1, 1210"
C7: library part CMP-0006848-4, "CAP, CERM, 0.01 uF, 100 V, +/- 5%, X7R, 0603"
C9: library part CMP-0007085-4, "CAP, CERM, 2200 pF, 100 V, +/- 10%, X7R, AEC-Q200 Grade 1, 0603"
C10: library part CMP-0007275-4, "CAP, CERM, 56 pF, 100 V, +/- 5%, C0G/NP0, 0603"
C11: library part CMP-0008656-2, "CAP, CERM, 47 uF, 25 V, +/- 20%, X5R, 1206_190"
C12: library part CMP-0079201-1, "CAP, CERM, 10 µF, 50 V,+/- 10%, X7R, 1210"
C13: library part CMP-0007575-2, "CAP, CERM, 0.33 uF, 25 V, +/- 10%, X5R, 0805"
C14: library part CMP-0006857-4, "CAP, CERM, 0.1 uF, 16 V, +/- 5%, X7R, 0603"
C15: library part CMP-0006268-2, "CAP, CERM, 4.7 uF, 10 V, +/- 10%, X5R, 0402"
C16: library part CMP-0006862-5, "CAP, CERM, 0.1 uF, 10 V, +/- 10%, X7R, 0603"
C17: library part CMP-0006844-4, "CAP, CERM, 1000 pF, 50 V, +/- 5%, X7R, AEC-Q200 Grade 1, 0603"
C18 C19 C24 C25: library part CMP-0006737-4, "CAP, CERM, 2200 pF, 100 V, +/- 10%, X7R, 0603"
C20 C21 C22 C23: library part CMP-0007475-4, "CAP, CERM, 2200 pF, 100 V, +/- 10%, X7R, 0603"
C26: library part CMP-0079150-1, "CAP, CERM, 0.1 µF, 10 V,+/- 10%, X7R, AEC-Q200 Grade 1, 0402"
C27 C28: library part CMP-0006834-5, "CAP, CERM, 470 pF, 50 V, +/- 10%, X7R, 0603"
C29 C30 C31: library part CMP-0006723-4, "CAP, CERM, 1000 pF, 100 V, +/- 5%, X7R, 0603"
D1 D2 D3 D7: library part CMP-0005527-4, "Diode, Zener, 16 V, 1 W, SMA"
D4 D5 D6 D8: library part CMP-0076923-3, "Diode, Schottky, 40 V, 2 A, SMA"
F1: library part CMP-0077200-3, "Fuse, 30 A, 250 VAC, 100 VDC, SMD"
FID1 FID2 FID3 FID4 FID5 FID6: library part CMP-0077181-1, "Fiducial mark.  There is nothing to buy or mount."
GHA1 GHB1 GLA1 GLB1 SHA1 SHB1: library part CMP-0055139-1, "Test Point, Miniature, White, TH"
GND: library part CMP-0055138-1, "Test Point, Miniature, Black, TH"
GND: library part CMP-0075110-1, "1mm Uninsulated Shorting Plug, 10.16mm spacing, TH"
H1 H2 H3 H4: library part CMP-0003621-1, "Bumpon, Cylindrical, 0.312 X 0.200, Black"
J1 J7 J8: library part CMP-0055527-1, "Terminal Block, 9.52mm, 2x1, R/A, TH"
J2 J6: library part CMP-0054796-2, "Header, 2.54 mm, 3x1, Gold, TH"
J3: library part CMP-0055060-1, "SOCKET .050\" GRID SIP 4 POS R/A, TH"
J4: library part CMP-0075409-2, "Header, 100mil, 4x1, Gold, TH"
J5: library part CMP-0054600-1, "Header, 2.54 mm, Gold, 7x1, TH"
L1: library part CMP-0057541-2, "Inductor, Drum Core, Ferrite, 68 uH, 1.1 A, 0.22 ohm, SMD"
LBL1: library part CMP-0003625-1, "Thermal Transfer Printable Labels, 0.650\" W x 0.200\" H - 10,000 per roll"
Logo1: library part CMP-0074844-1
Logo2: library part CMP-0074838-1, "Texas Instrument Corporate Signature"
Logo3: library part CMP-0074847-1, "FCC_disclaimer"
Logo4: library part CMP-0074769-1
LOGO5 LOGO6: library part CMP-0074837-1, "IEC 61010-1 Hot Surface Warning"
LOGO7 LOGO8: library part CMP-0074835-1, "IEC 61010-1 High Voltage Warning"
NT1 NT2 NT3 NT4: library part CMP-0078142-4, "Single point connection between nets."
Q1 Q2 Q3 Q4: library part CMP-0000958-3, "MOSFET, N-CH, 100 V, 17 A, DNK0008A (VSON-CLIP-8)"
R1 R19 R34 R45: library part CMP-0020617-3, "RES, 10, 5%, 0.125 W, AEC-Q200 Grade 0, 0805"
R2 R17 R25 R31: library part CMP-0020521-3, "RES, 2.7, 5%, 0.125 W, AEC-Q200 Grade 0, 0805"
R3 R11 R12 R13 R16: library part CMP-0025697-4, "RES, 0, 5%, 0.1 W, AEC-Q200 Grade 0, 0603"
R4: library part CMP-0025736-4, "RES, 1.0 M, 5%, 0.1 W, AEC-Q200 Grade 0, 0603"
R5: library part CMP-0023236-4, "RES, 681 k, 1%, 0.1 W, 0603"
R6: library part CMP-0023120-4, "RES, 453 k, 1%, 0.1 W, 0603"
R7: library part CMP-0025784-4, "RES, 330 k, 5%, 0.1 W, AEC-Q200 Grade 0, 0603"
R8: library part CMP-0025950-3, "RES, 100 k, 1%, 0.063 W, AEC-Q200 Grade 0, 0402"
R9: library part CMP-0023142-5, "RES, 49.9 k, 1%, 0.1 W, 0603"
R10: library part CMP-0020443-3, "RES, 0, 5%, 0.333 W, AEC-Q200 Grade 0, 0805"
R14 R20: library part CMP-0025785-4, "RES, 330, 5%, 0.1 W, AEC-Q200 Grade 0, 0603"
R15: library part CMP-0025814-4, "RES, 47 k, 5%, 0.1 W, AEC-Q200 Grade 0, 0603"
R18 R21 R24 R29 R37 R38: library part CMP-0021990-4, "RES, 100 k, 1%, 0.1 W, AEC-Q200 Grade 0, 0603"
R22 R27 R46 R47: library part CMP-0020643-3, "RES, 15, 5%, 0.125 W, AEC-Q200 Grade 0, 0805"
R23 R28 R35 R36 R39 R40 R41 R42 R43 R44 R48 R49 R50: library part CMP-0081973-1, "RES, 0, 0%, 0.25 W, AEC-Q200 Grade 0, 0603"
R26 R33: library part CMP-0015826-2, "RES, 0.002, 1%, 3 W, AEC-Q200 Grade 0, 2512"
R30 R32: library part CMP-0022458-4, "RES, 4.99 k, 1%, 0.1 W, AEC-Q200 Grade 0, 0603"
RP1 RP2 RP3: library part CMP-0001777-2, "Trimming Potentiometer, 50K, 0.5W, TH"
SH-J1 SH-J2: library part CMP-0003623-3, "Shunt, 100mil, Gold plated, Black"
TP1 TP2: library part CMP-0003825-1, "1mm Test Point, SMT"
U1: library part CMP-0091750-2, "100-V Brushed DC Gate Driver"
U2: library part CMP-0066087-1, "7.5-100V Wide Vin, 600mA Constant On-Time Synchronous Buck Regulator, NGU0008B (WSON-8)"
U3: library part CMP-0080825-1, "500-mA, 25-V, Linear Voltage Regulators, DCY0004A (SOT-223-4)"
U4: library part CMP-0039637-1, "16 MHz Mixed Signal Microcontroller with 16 KB Flash, 512 B SRAM and 24 GPIOs, -40 to 85 degC, 20-pin SOP (PW), Green (RoHS & no Sb/Br)"
U5: library part CMP-0013323-2, "Bidirectional, Low- and High-Side Measurement, Multichannel, Voltage Output, Current-Sense Amplifiers, DGS0010A (VSSOP-10)"
U6: library part CMP-0081556-1, "Low-Power, Rail-to-Rail In and Out, 1-MHz Operational Amplifier, DCK0005A (SOT-SC70-5)"
ZZ1: library part CMP-0003616-3
ZZ2: library part CMP-0077236-1
ZZ3: library part CMP-0077237-1
ZZ4: library part CMP-0077238-1

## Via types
v1: diameter 25, hole 12, Top Layer to Bottom Layer, tented both sides, 566 vias
v2: diameter 19.68, hole 7.87, Top Layer to Bottom Layer, 9 vias
v3: diameter 26, hole 12, Top Layer to Bottom Layer, tented both sides, 4 vias

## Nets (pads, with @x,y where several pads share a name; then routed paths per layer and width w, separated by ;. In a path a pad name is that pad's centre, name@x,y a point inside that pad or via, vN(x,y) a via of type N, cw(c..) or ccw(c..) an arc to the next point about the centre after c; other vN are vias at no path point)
3.3V: 3.3V.1 C15.1 C16.1 C26.1 R13.2 R15.2 R16.2 R37.2 RP1.3 RP2.3 RP3.3 U4.1 U5.10 U6.5 | length 5397.5
  Top Layer w10: v1(2042.81,414.23) C26.1@2042.81,381.66 2059.15,381.66 2078.25,400.75 U5.10@2112.01,400.75
  Top Layer w12: C16.1@468.5,873.03 U4.1@602.36,873.03 599.41,875.98 C15.1@521.65,875.98 ; 3.3V.1@482.89,1764.59 v1(537.98,1764.59) ; U6.5@1750.79,397.35 1750.32,396.87 v1(1750.32,350.36) 1910.64,350.36 R37.2@1919.29,341.72
  Top Layer w20: v1(397.07,875.98) 466.54,875.98 C16.1@468.5,877.95 519.68,877.95 C15.1@521.65,875.98 ; v1(633.86,374.02) R16.2@712.4,374.02 R15.2@813.88,374.02 ; 3.3V.1@856.3,1564.22 949.56,1564.22 R13.2@980.64,1533.14
  Signal Layer 2 w20: v1(397.07,875.98) 177.17,875.98 ; 3.3V.1@856.3,1564.22 655.93,1764.59 v1(537.98,1764.59) 306.89,1533.49 RP1.3@110.65,1533.49 167.32,1476.82 167.32,1074.41 RP2.3@108.27,1015.35 177.17,946.46 177.17,875.98 ; v1(2042.81,414.23) 1978.94,350.36 v1(1750.32,350.36) 1631.19,350.36 1583.1,302.27 705.6,302.27 v1(633.86,374.02) 220.32,374.02 RP3.3@108.3,486.04 177.17,554.9 177.17,875.98
3.3V_SBW: J3.4 J4.4 R16.1 | length 387.7
  Top Layer w12: R16.1@712.4,314.96 835.83,191.54 J3.4@835.83,137.8
  Signal Layer 2 w12: J4.4@681.75,150.63 822.99,150.63 J3.4@835.83,137.8
GHA: R19.1 R27.1 U1.19 | length 1451
  Top Layer w10: U1.19@2085.44,1155.03 2095.87,1155.03 v1(2116.14,1175.3)
  Top Layer w20: v3(2676.9,1646.31) 2675.17,1648.04 2695.39,1668.26 R27.1@3003.97,1668.26
  Bottom Layer w12: v1(2116.14,1175.3) 2116.14,1448.08 2198.03,1529.97 2674.06,1529.97 2738.94,1594.85 R19.1@2738.94,1648.04
  Bottom Layer w20: v3(2676.9,1646.31) 2737.21,1646.31 R19.1@2738.94,1648.04
GHB: R1.1 R22.1 U1.16 | length 1205.3
  Top Layer w10: U1.16@2111.03,1090.07 2135.83,1090.07 2145.67,1080.23 v1(2169.24,1080.23)
  Top Layer w20: v3(2658,843.03) 2658,846.57 2682.24,870.82 R22.1@3044.88,870.82
  Bottom Layer w12: v1(2169.24,1080.23) 2333.64,1080.23 2345.22,1068.65 2614.4,1068.65 2658,1025.04 v3(2658,843.03)
  Bottom Layer w20: v3(2658,843.03) 2706.22,843.03 R1.1@2706.69,843.5
GLA: R34.1 R47.1 U1.11 | length 502
  Top Layer w10: v1(2065.75,954.72) U1.11@2065.75,1005.42
  Bottom Layer w20: v1(2065.75,954.72) 2183.12,837.35 R47.1@2381.89,837.35 R34.1@2381.89,750.78
GLB: R45.1 R46.1 U1.10 | length 830
  Top Layer w10: v1(2026.38,967.82) 2046.07,987.51 U1.10@2046.07,1005.42
  Bottom Layer w20: v1(2026.38,967.82) 2026.38,867.32 2381.89,511.81 R45.1@2381.89,421.47 R46.1@2381.89,330.82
